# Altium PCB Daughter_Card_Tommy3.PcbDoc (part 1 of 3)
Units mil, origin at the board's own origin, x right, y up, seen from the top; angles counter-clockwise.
Board outline 2032.68 x 3237.01 mil, 8 copper layers (Top Layer, GND, AUX Routing (LVDS), 2.5V, AUX Route Vert, AUX Route Horz, GND (Plane2), Bottom Layer), stack 61.2 mil thick; 218 components, 194 nets, 1097 pads, 500 vias.
Unrouted connection lines stored in the file: 161.
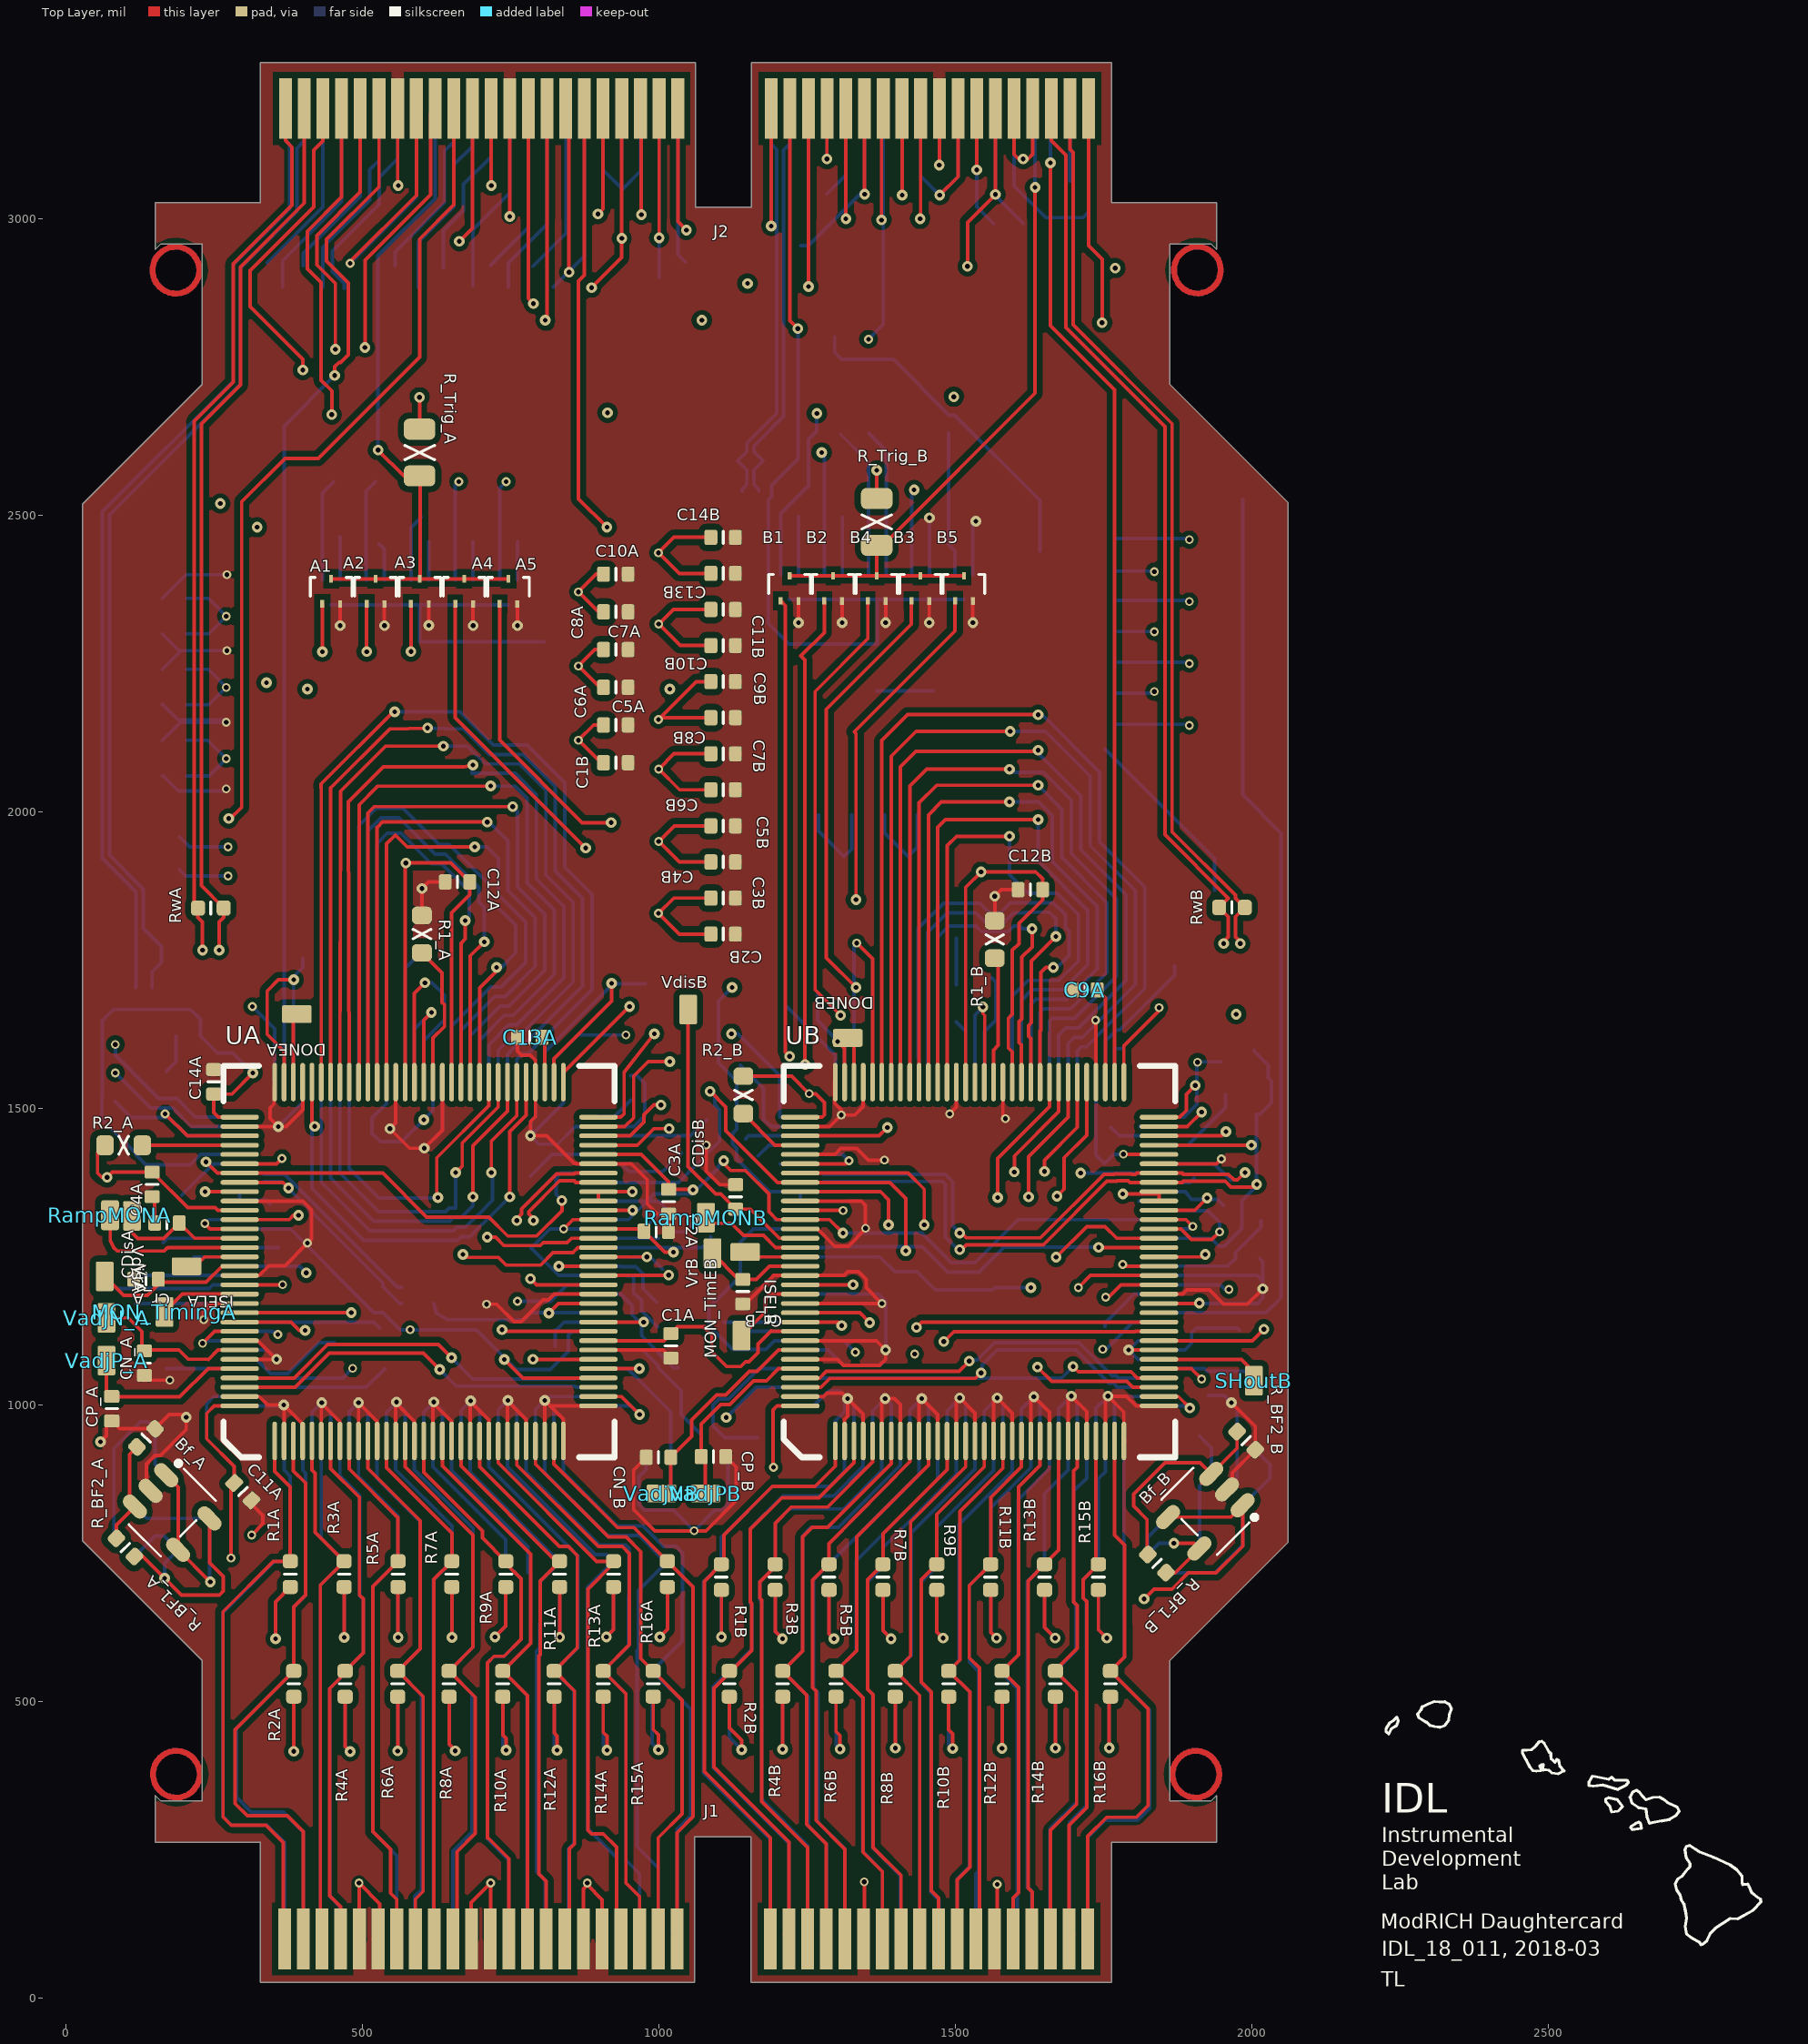
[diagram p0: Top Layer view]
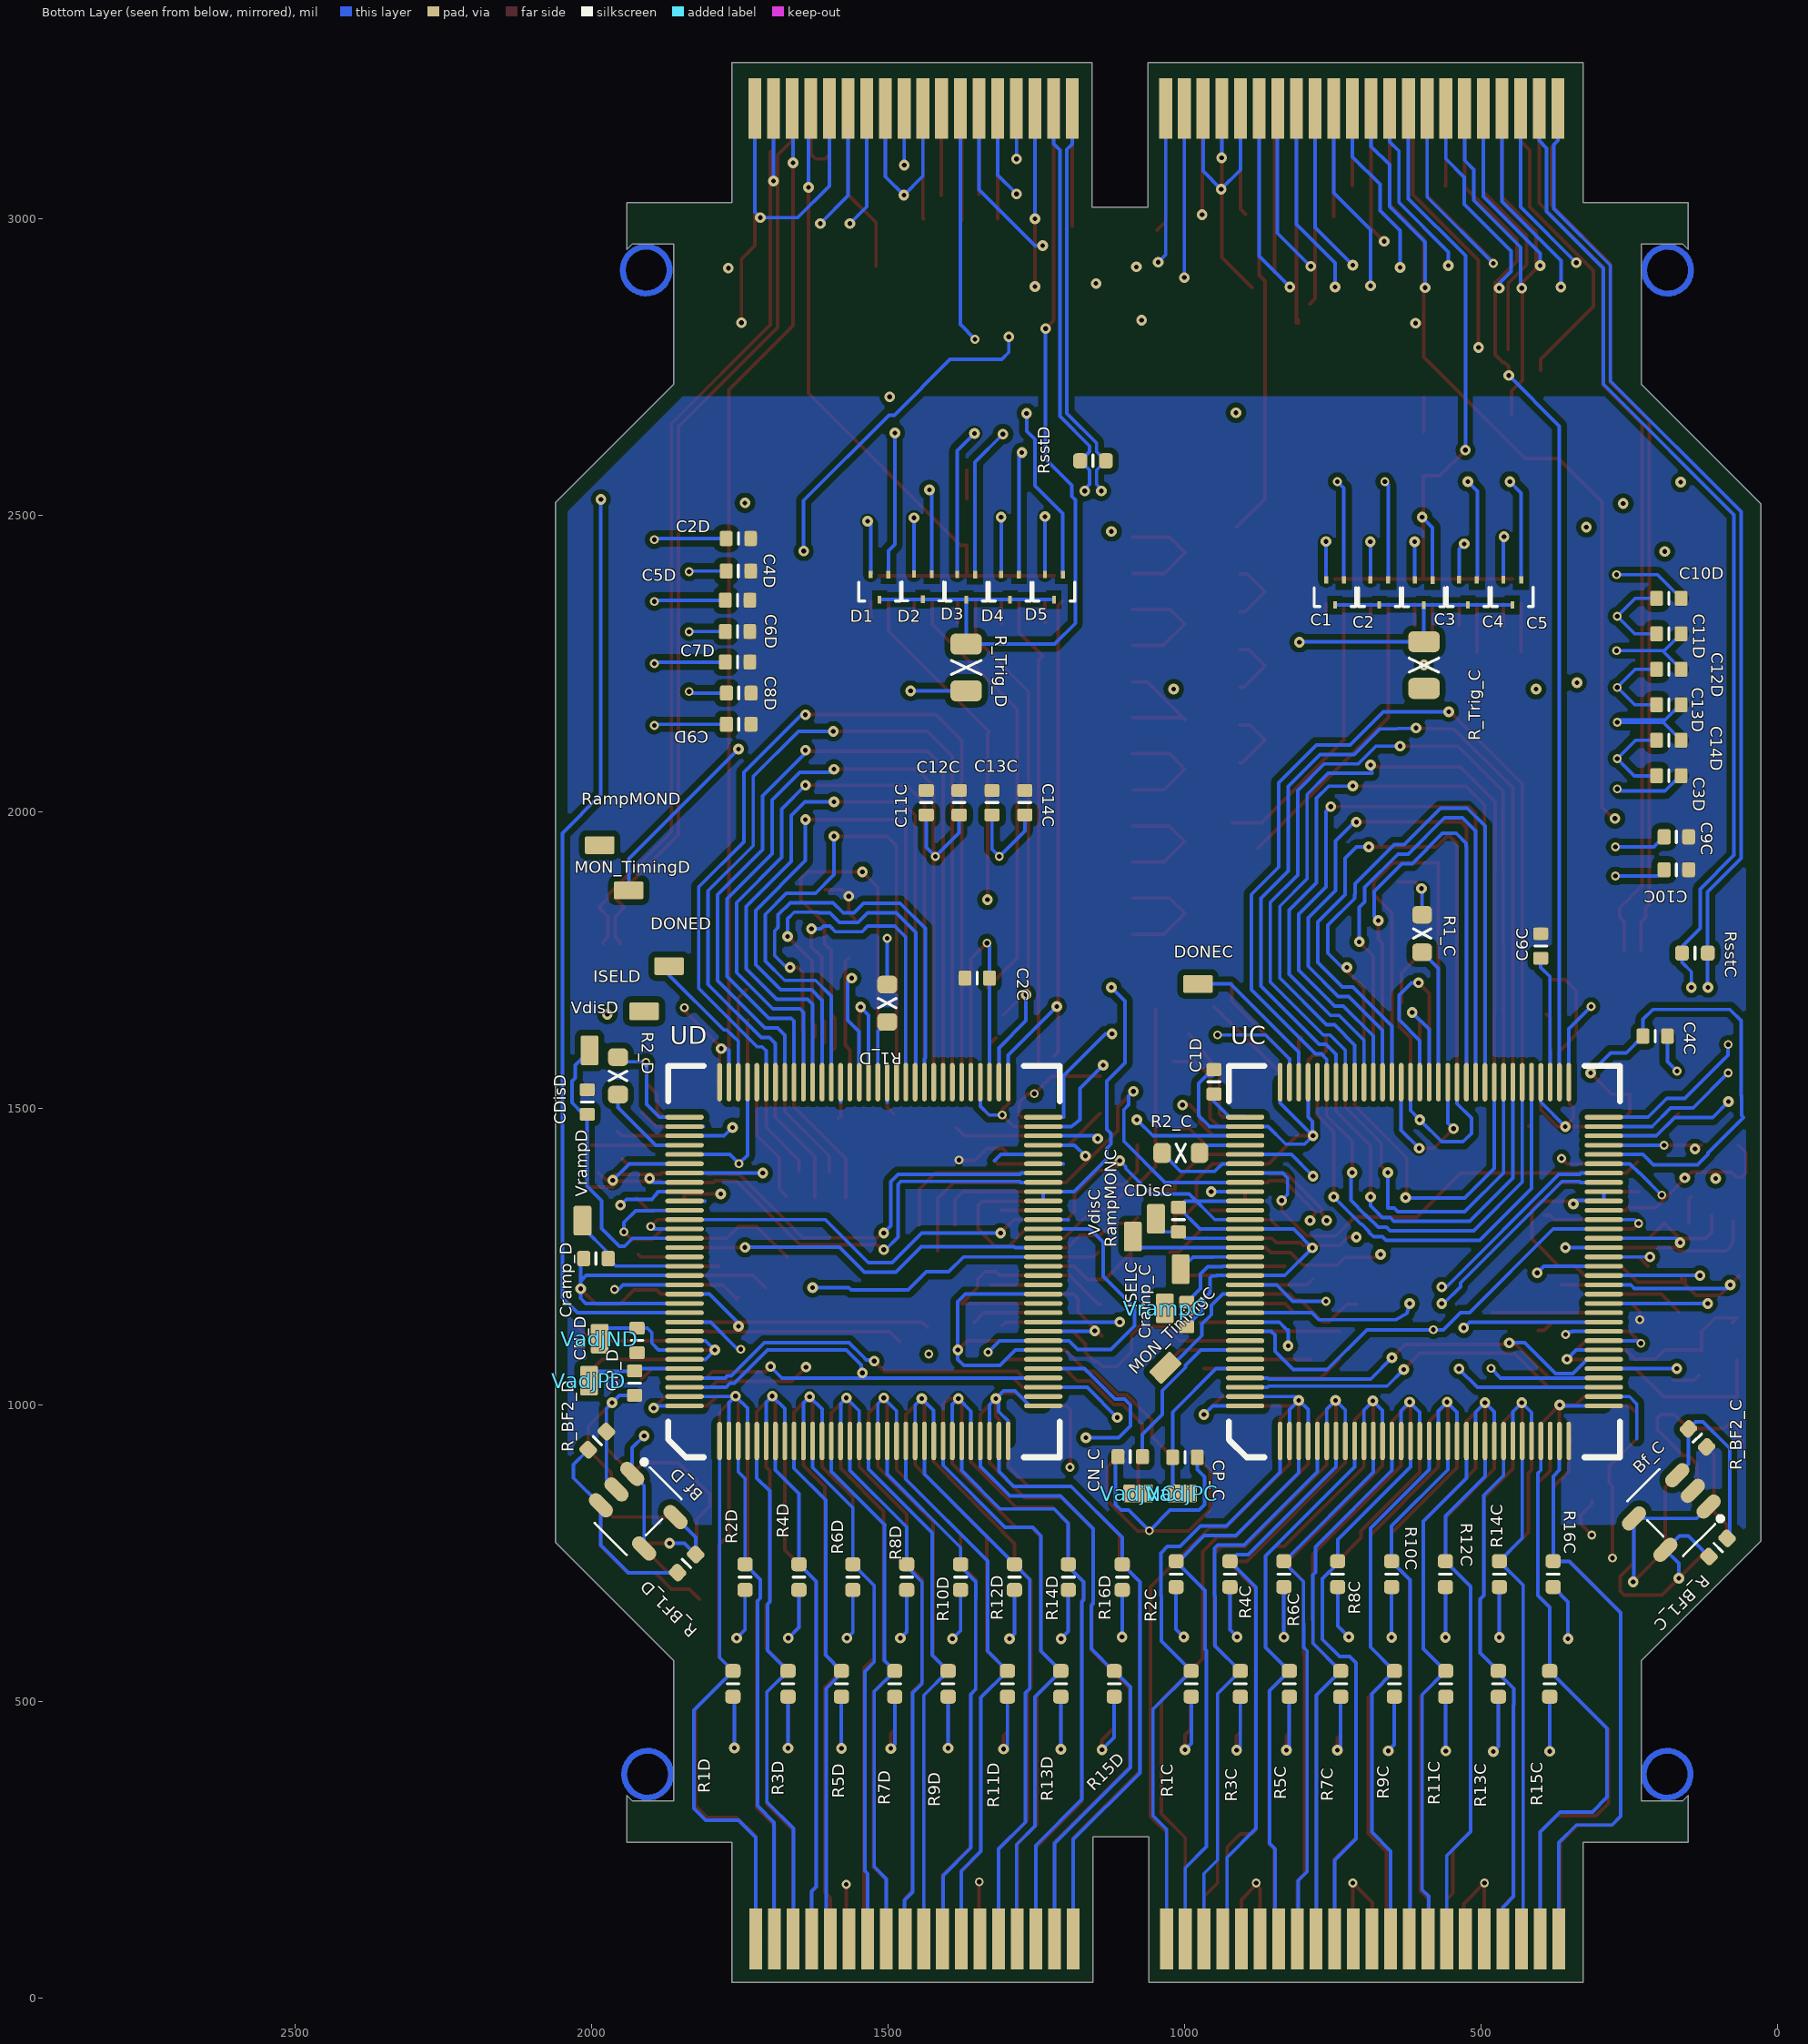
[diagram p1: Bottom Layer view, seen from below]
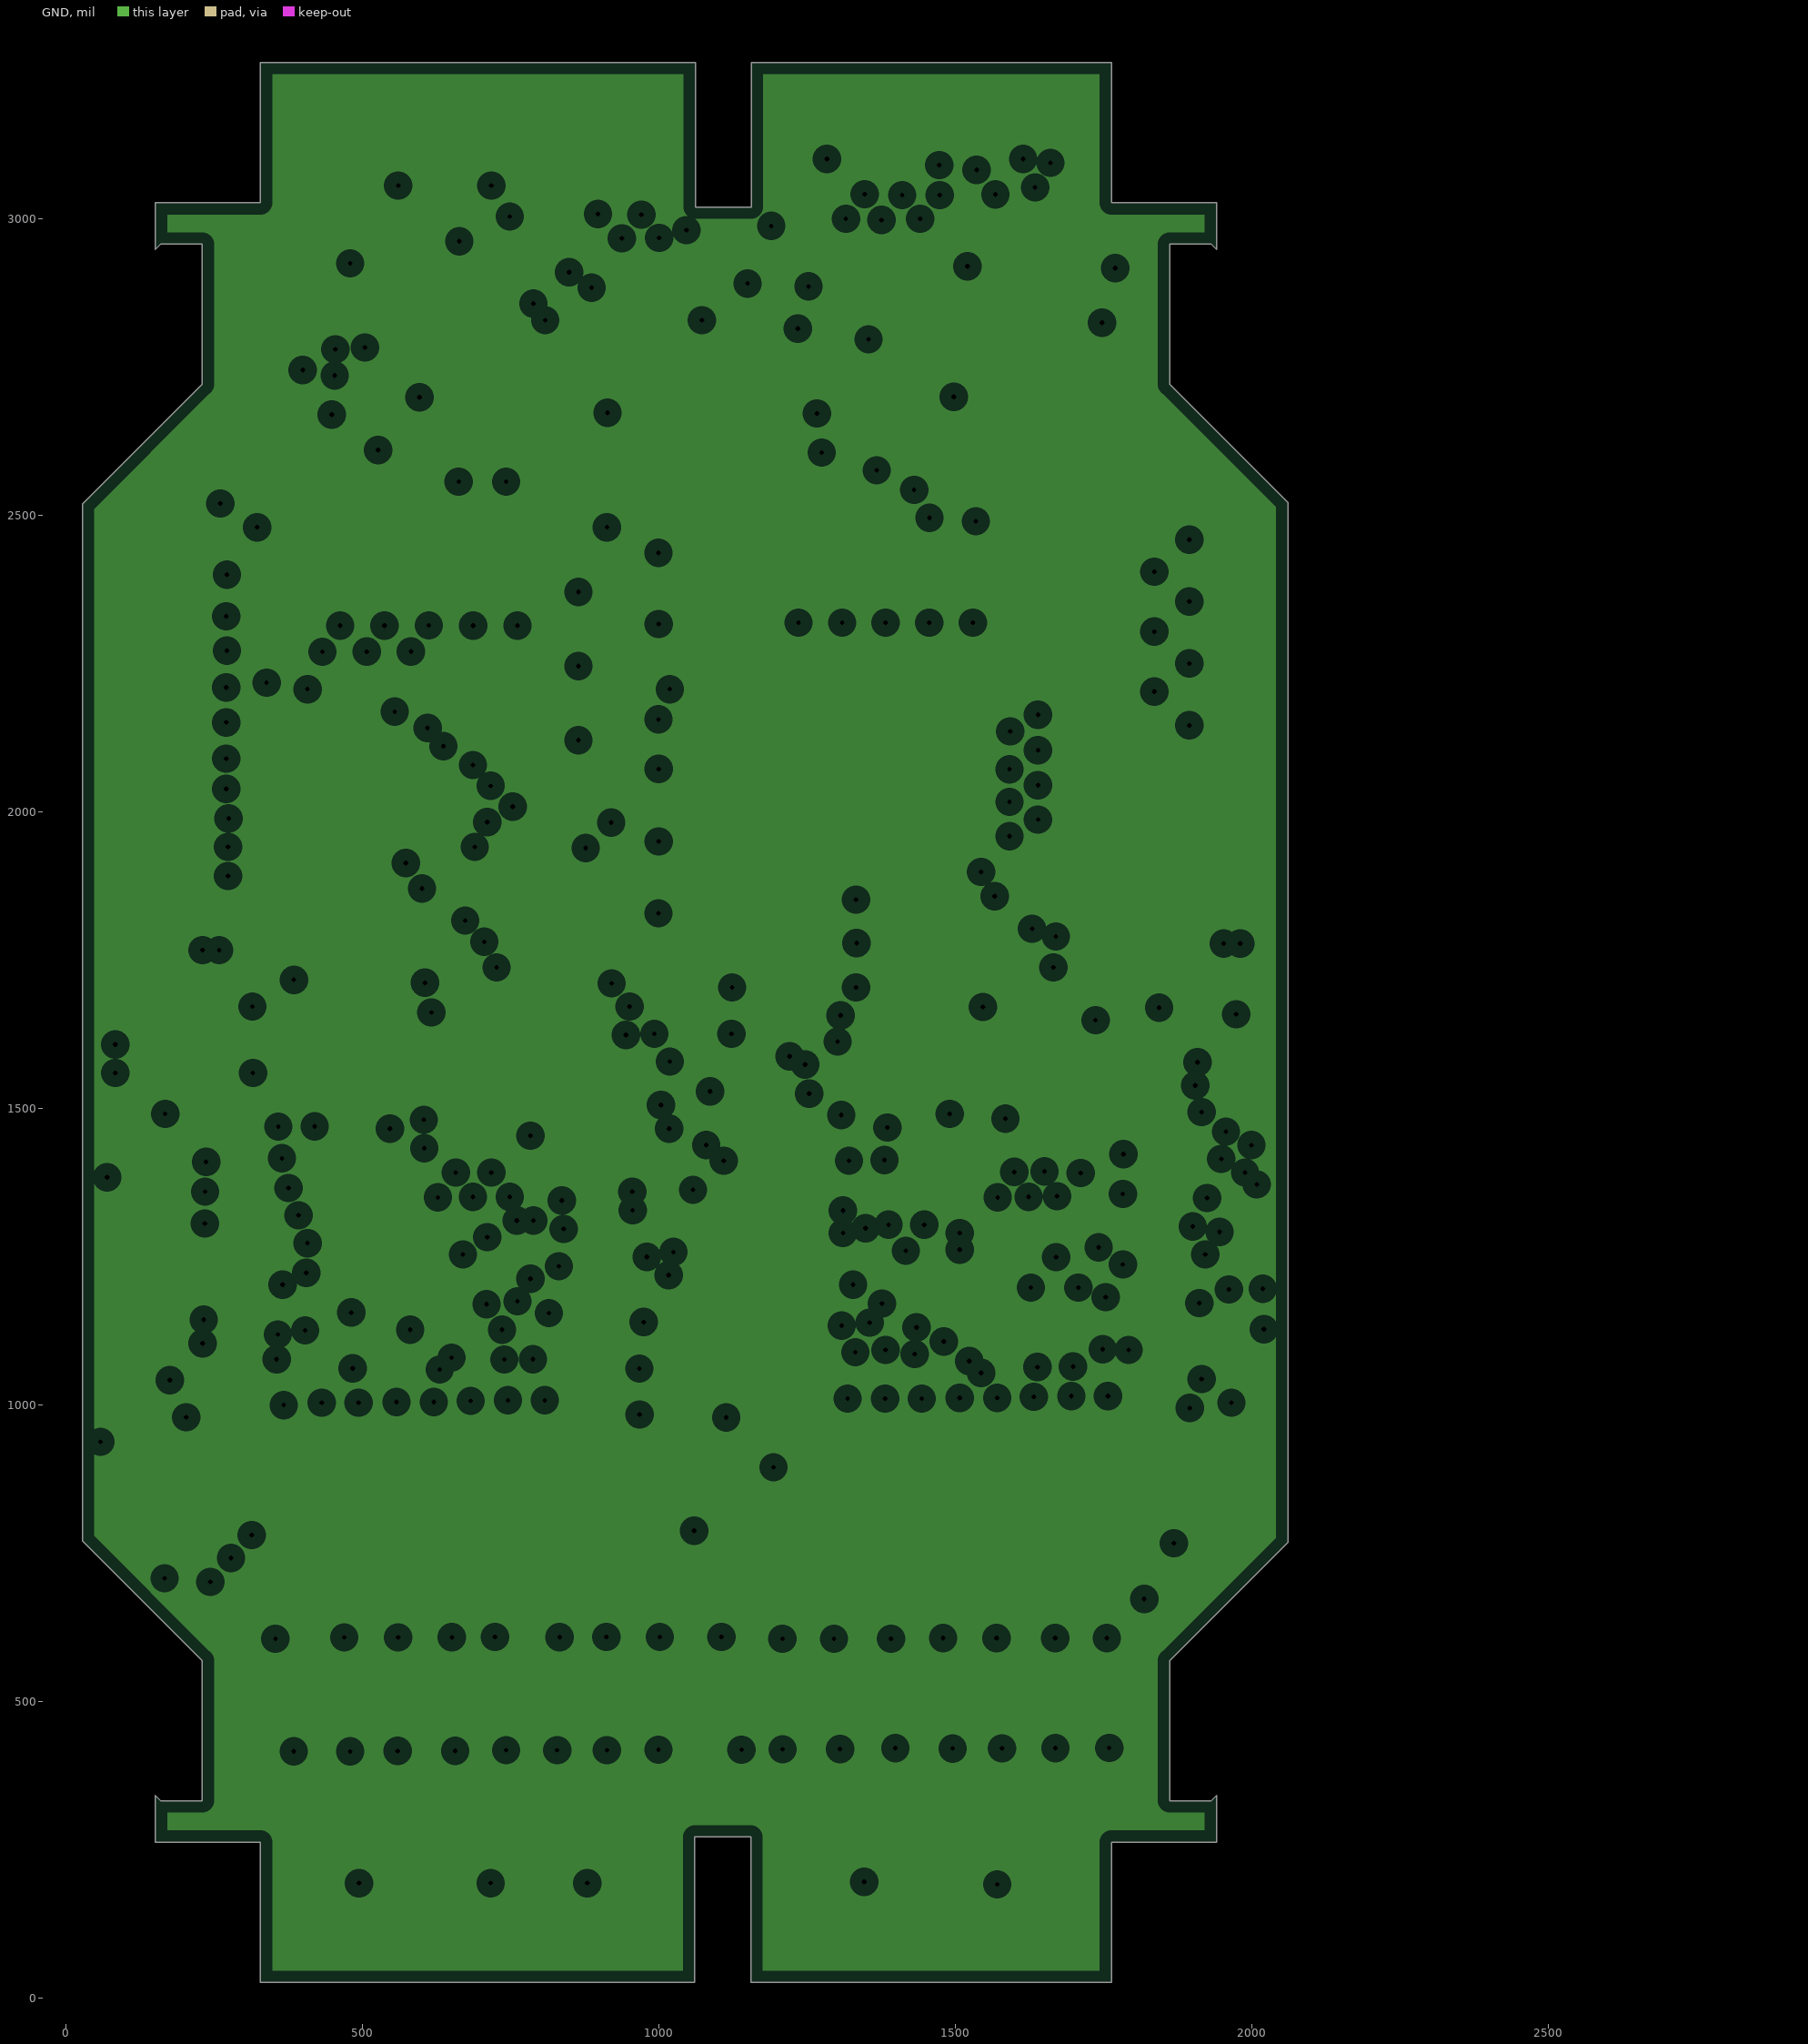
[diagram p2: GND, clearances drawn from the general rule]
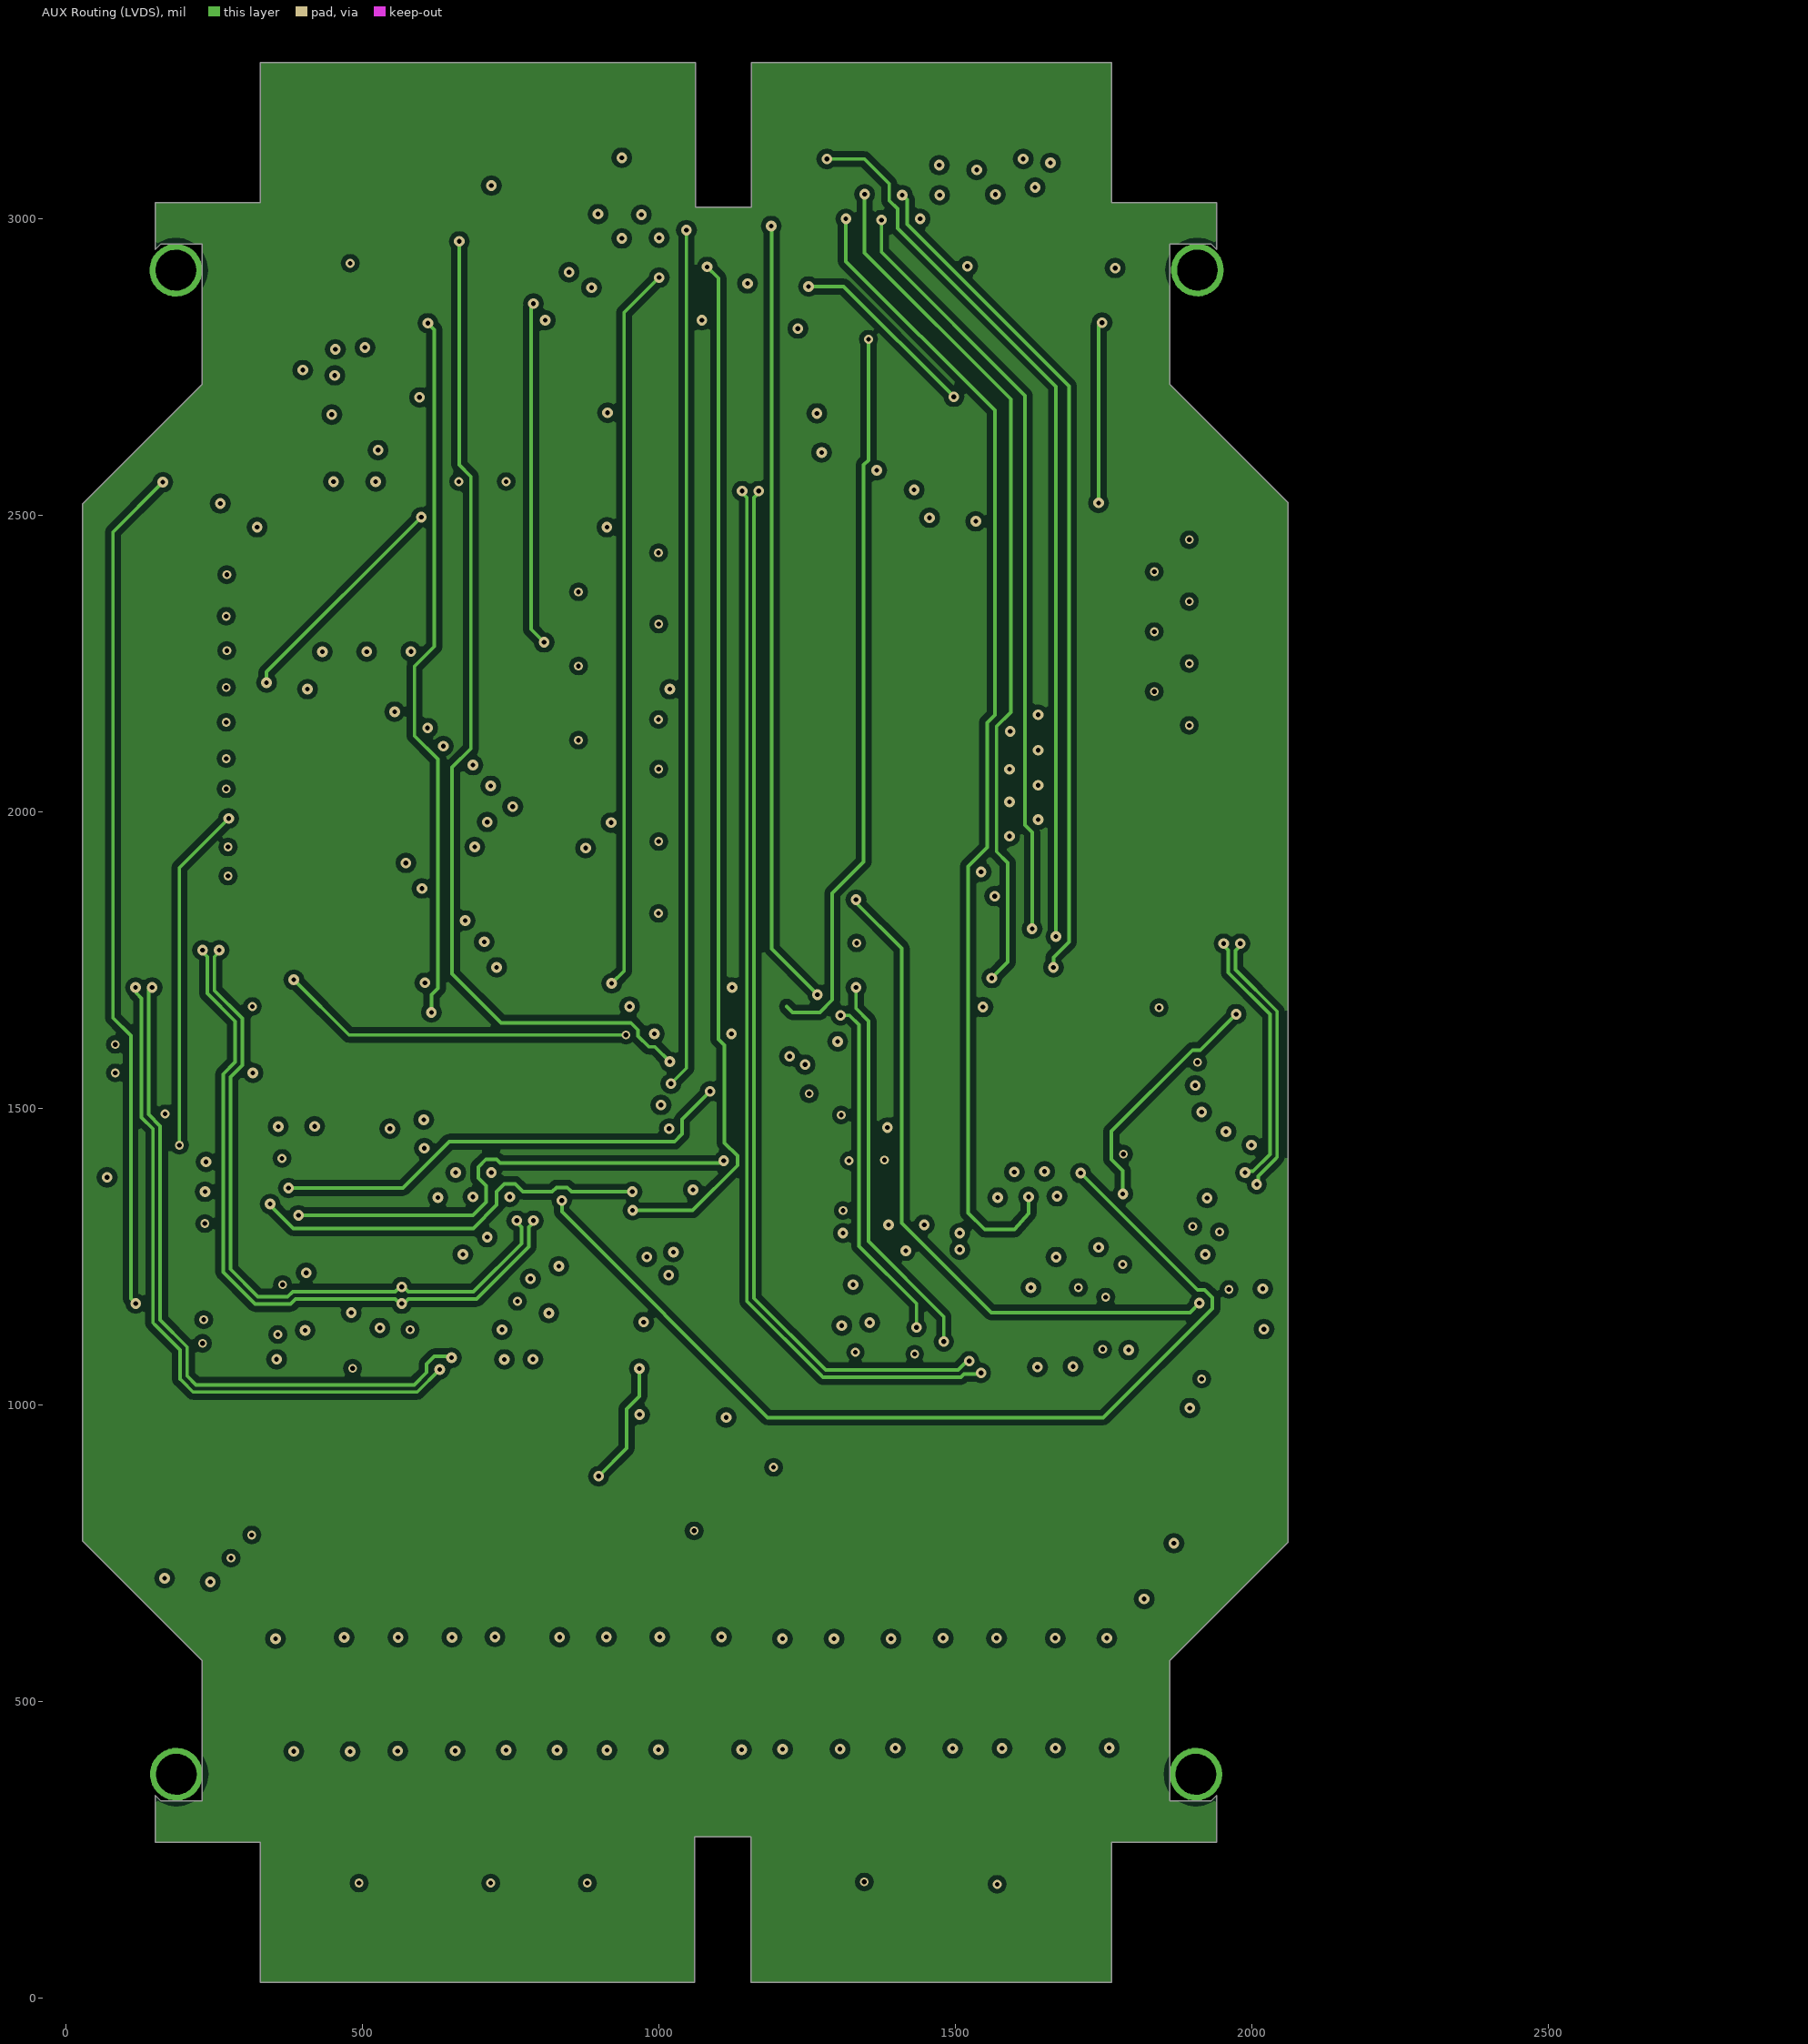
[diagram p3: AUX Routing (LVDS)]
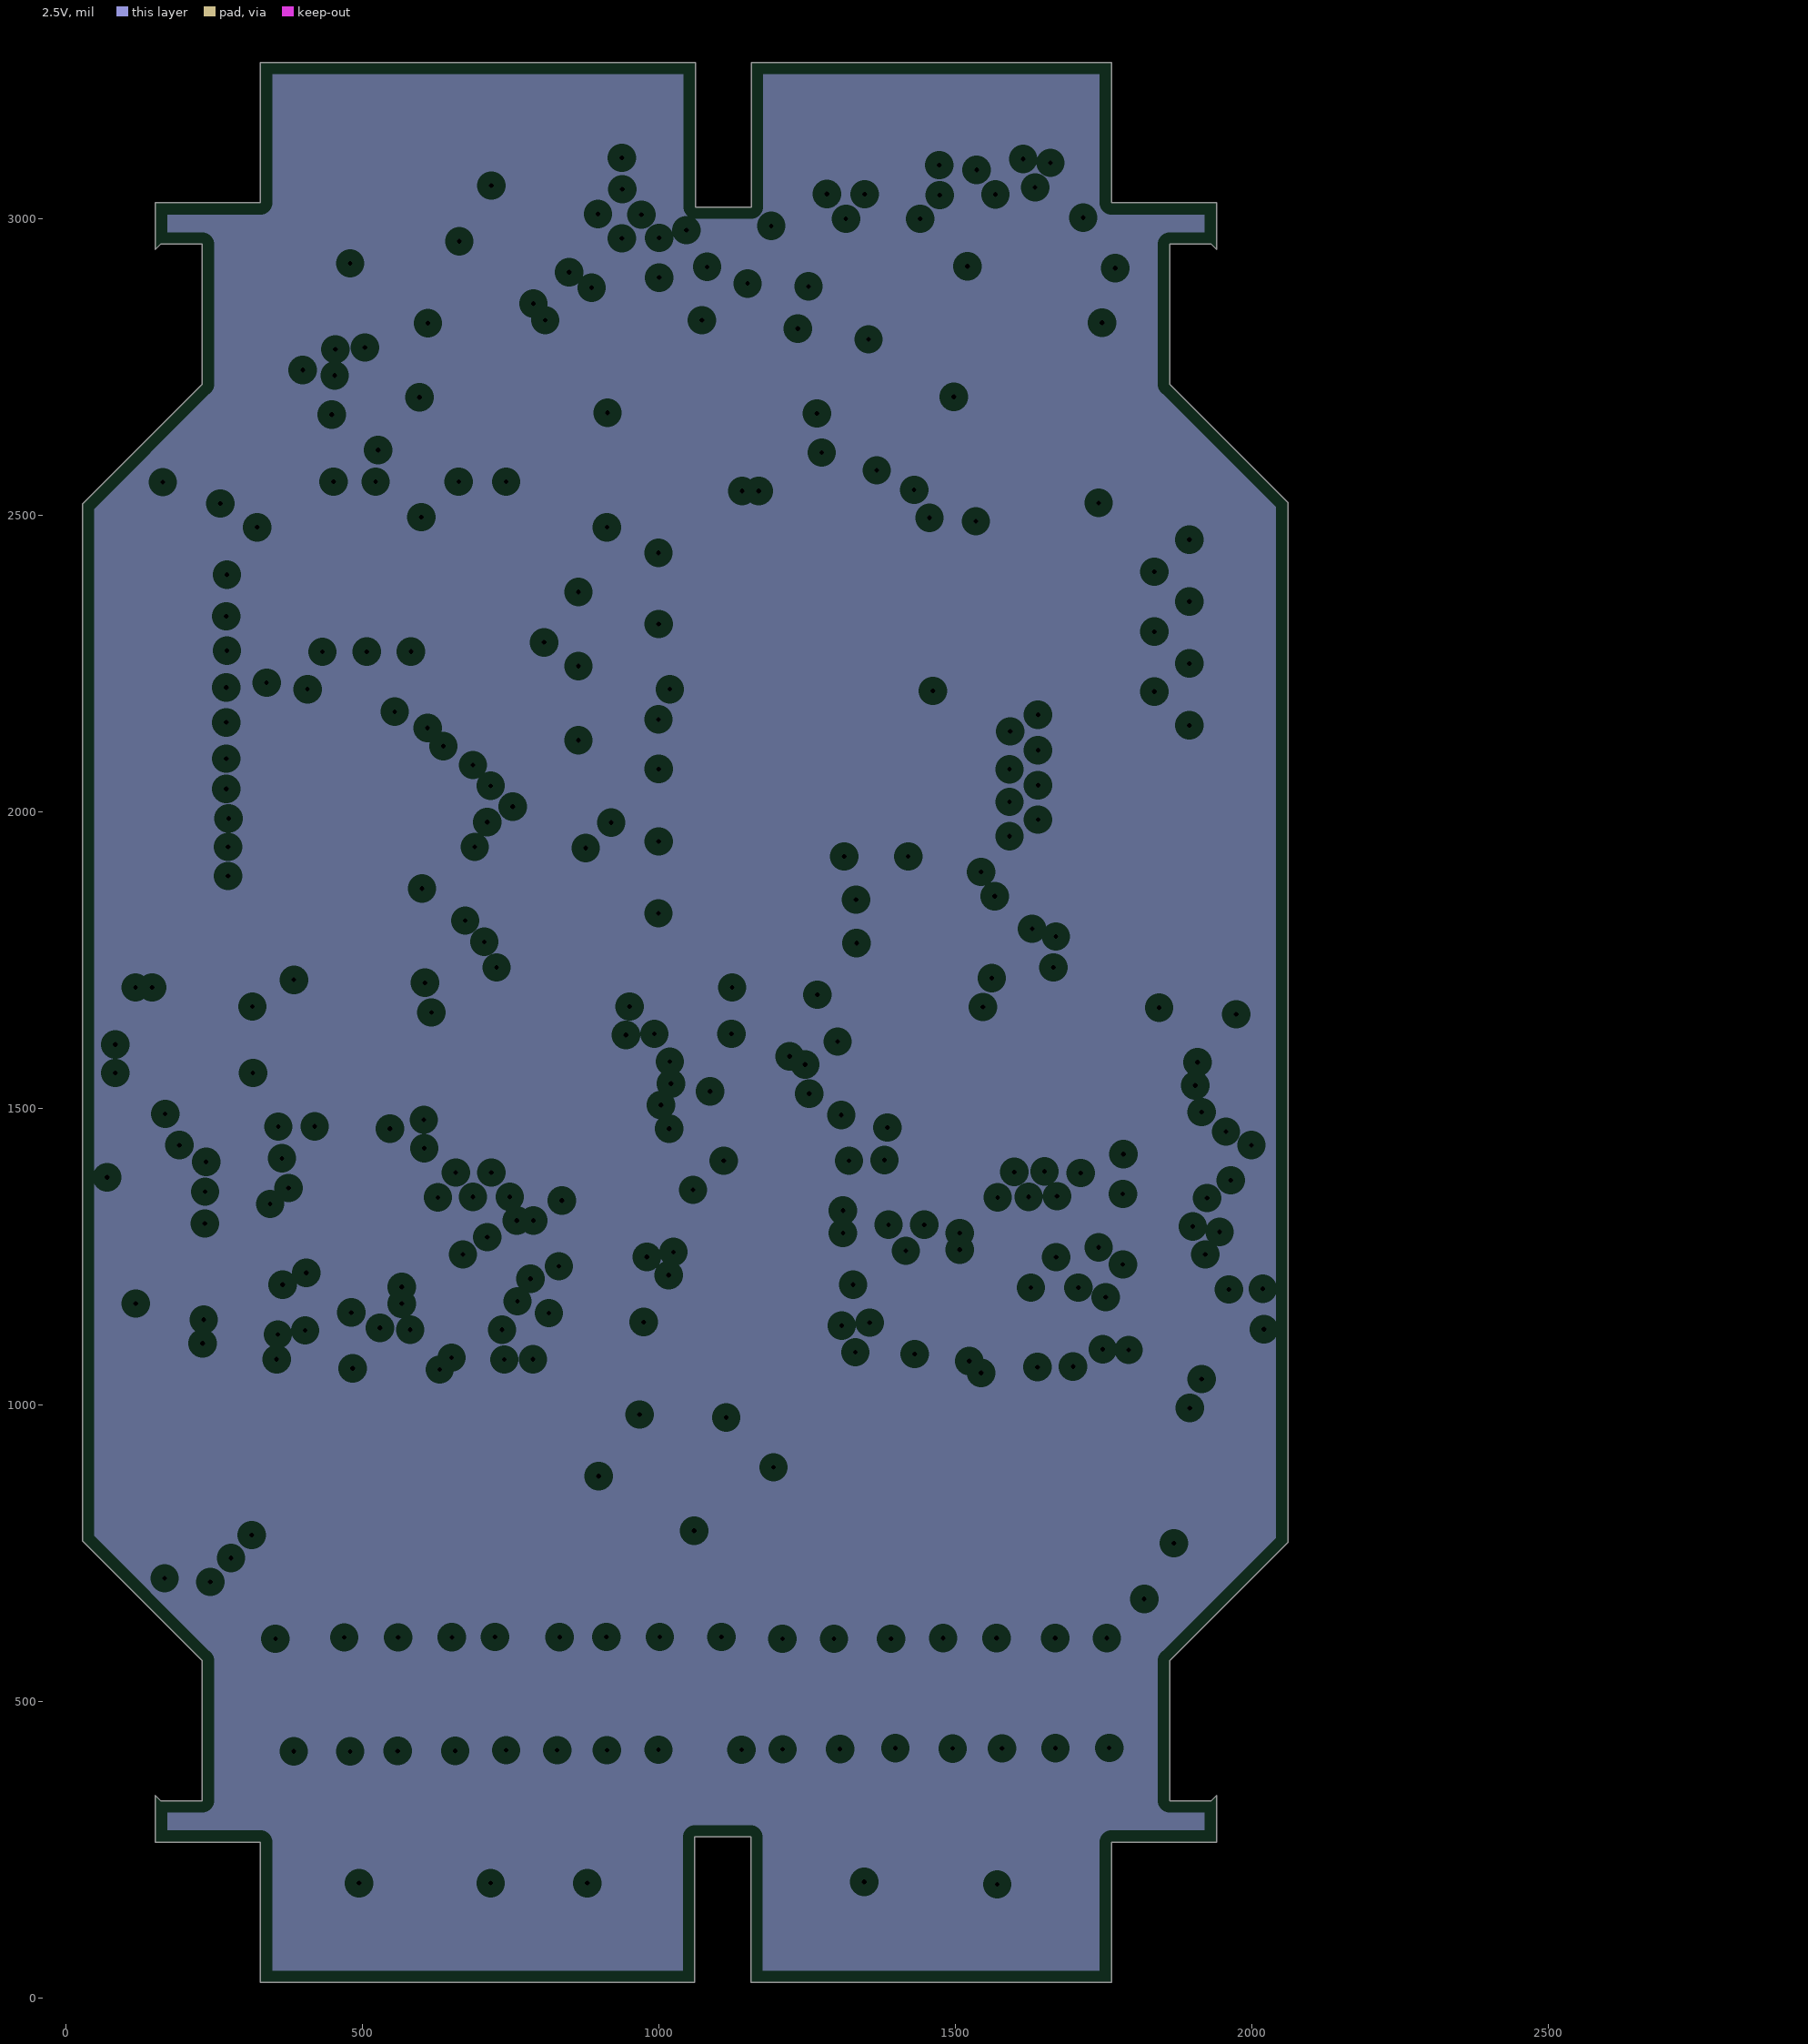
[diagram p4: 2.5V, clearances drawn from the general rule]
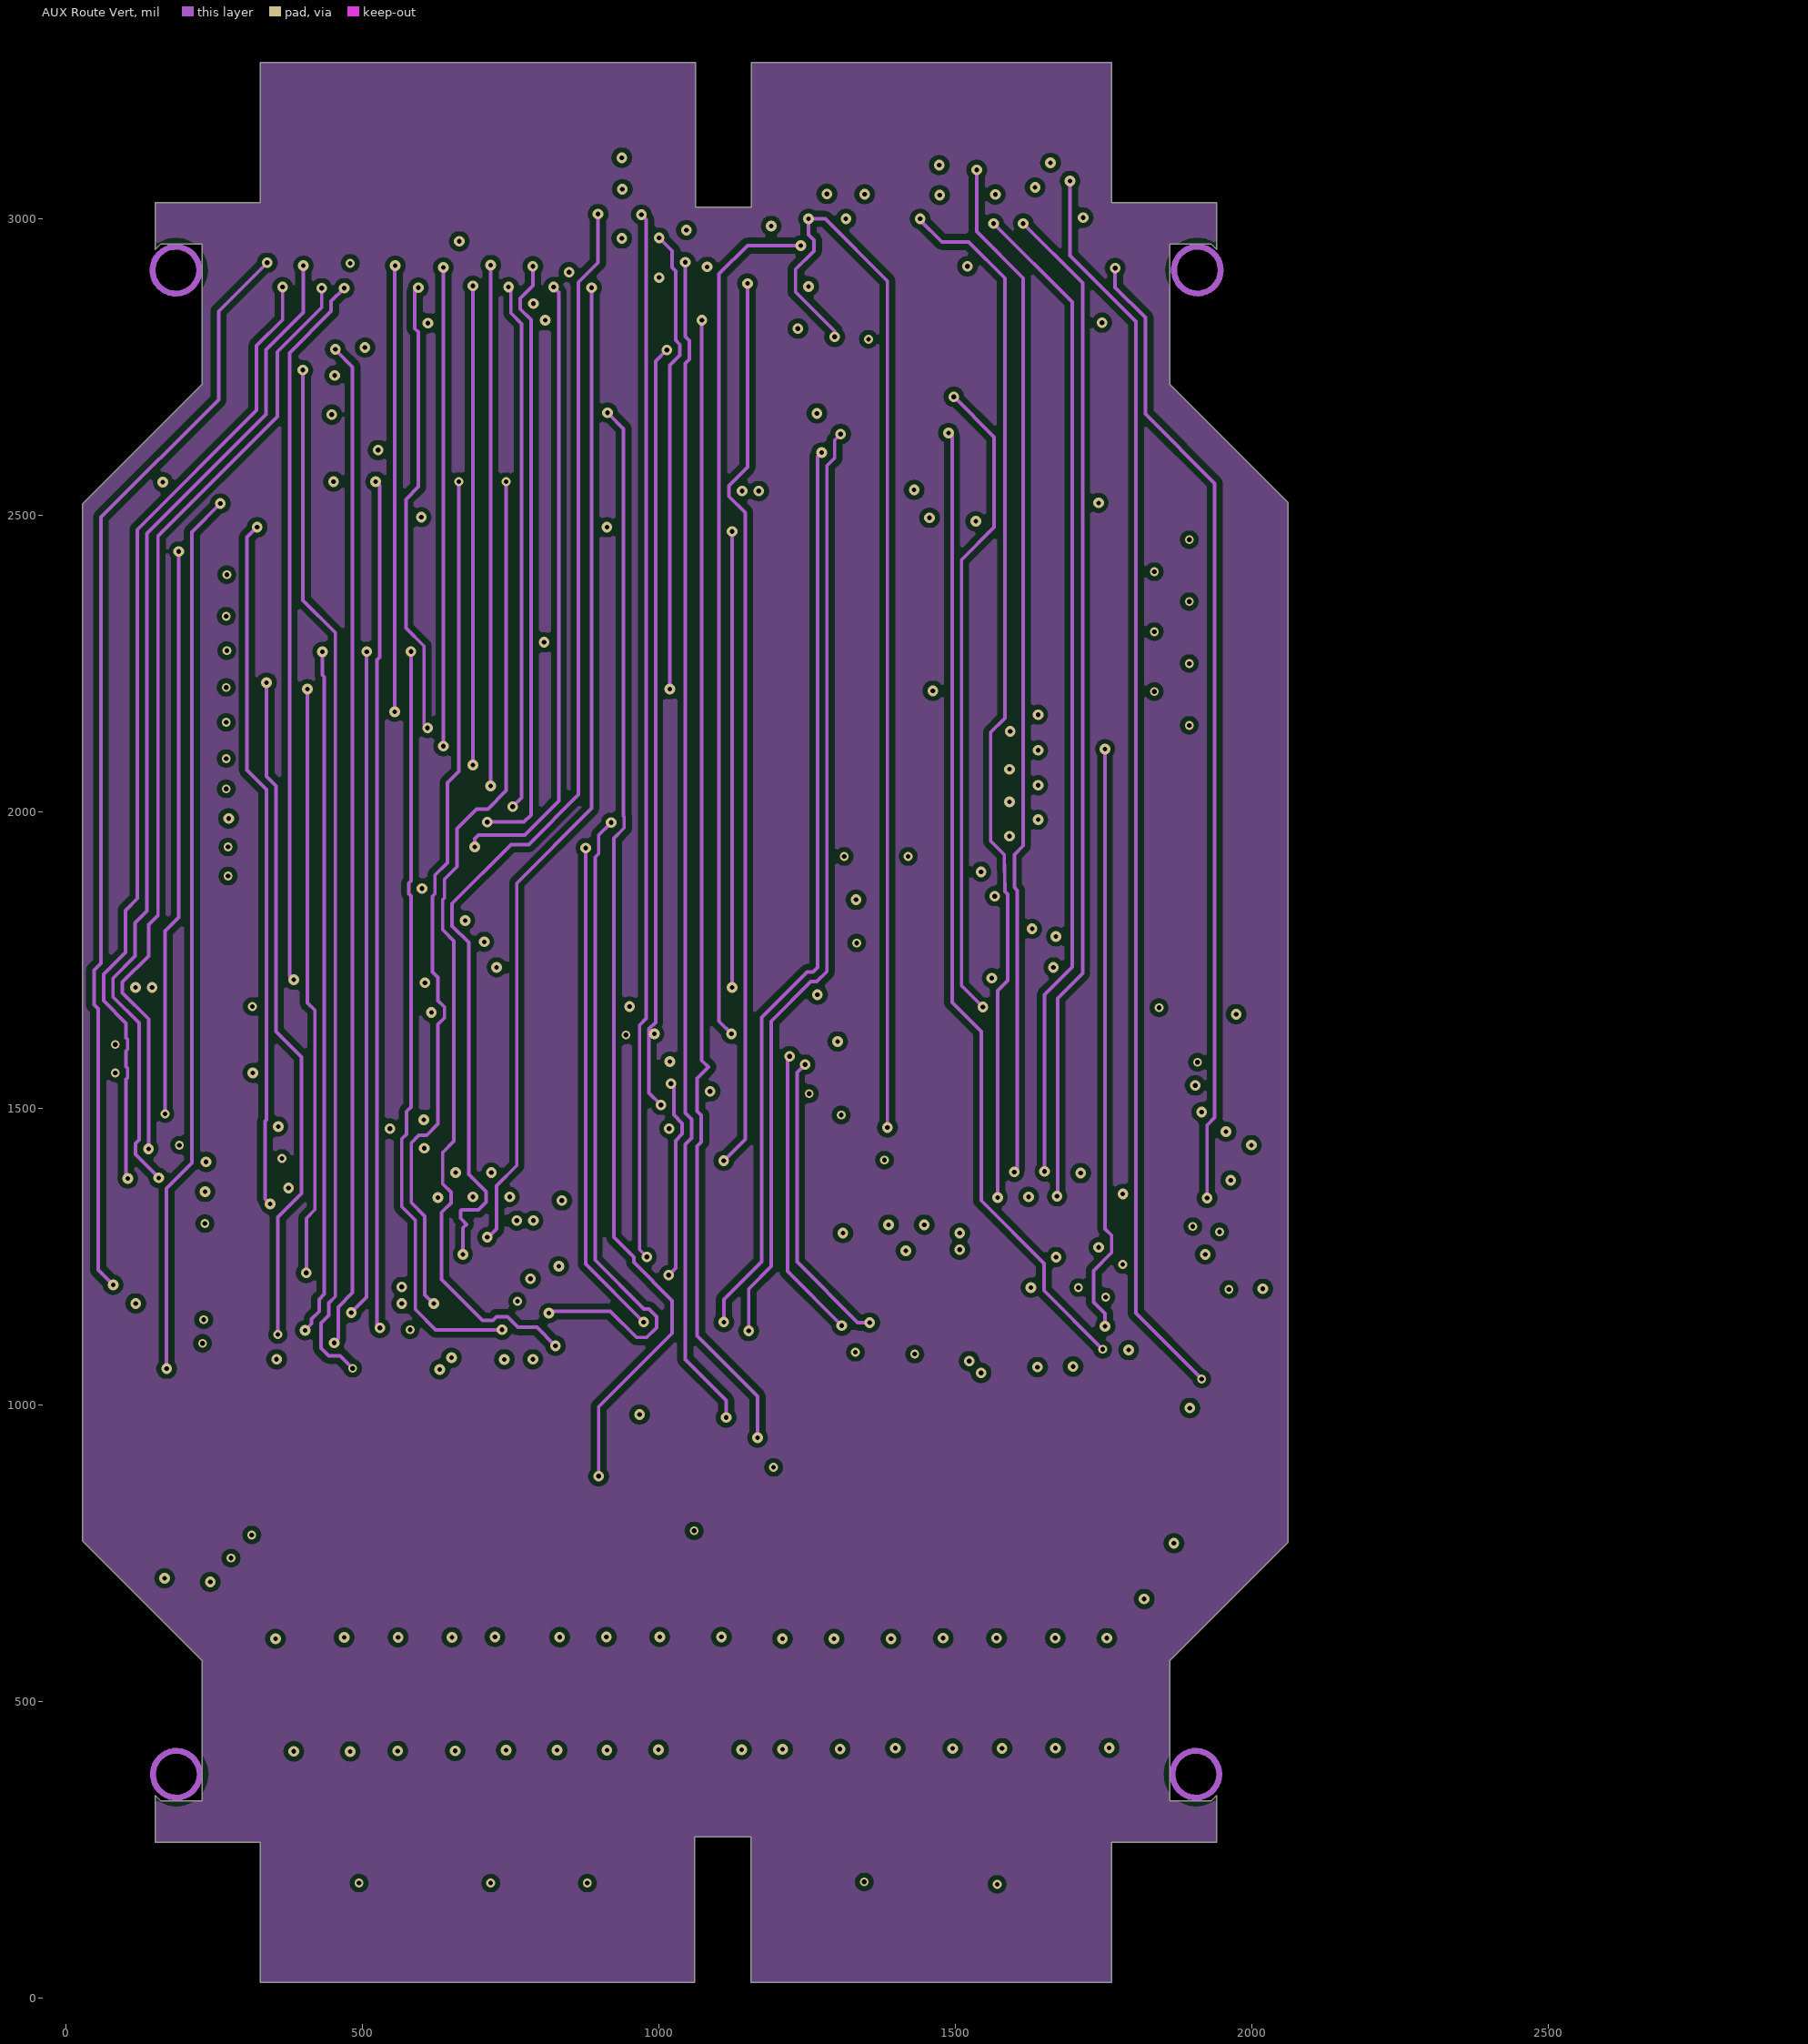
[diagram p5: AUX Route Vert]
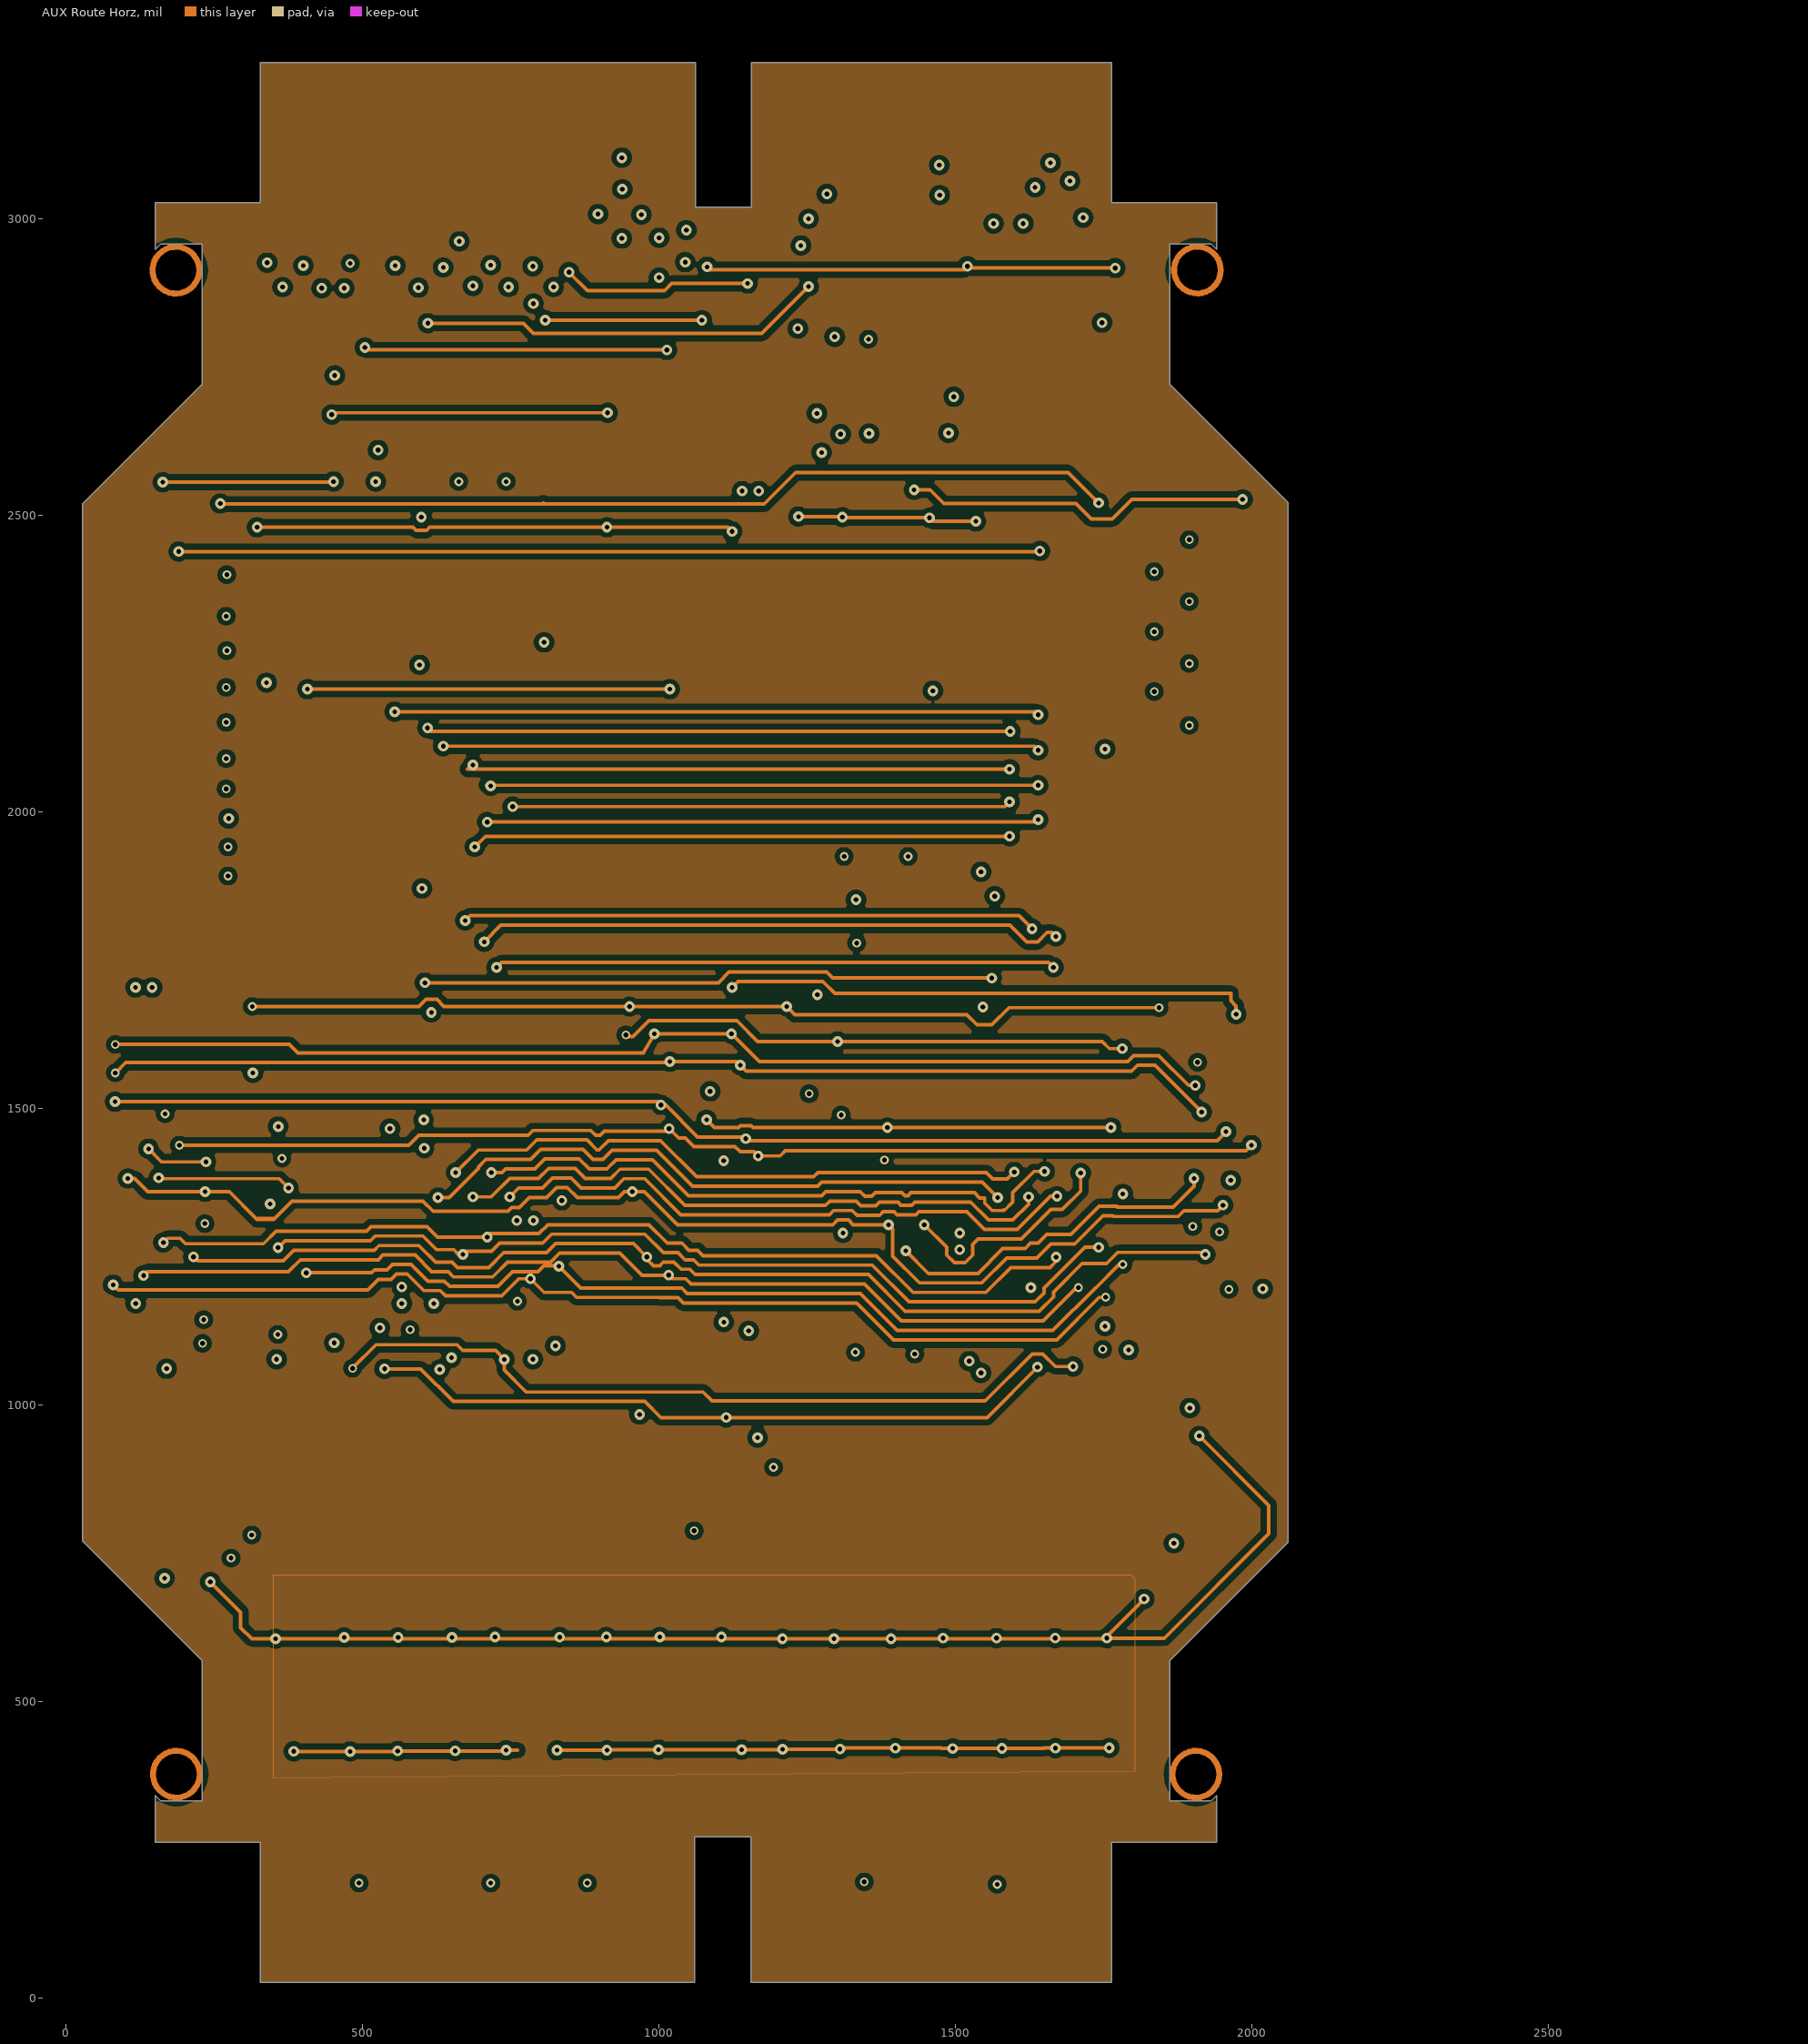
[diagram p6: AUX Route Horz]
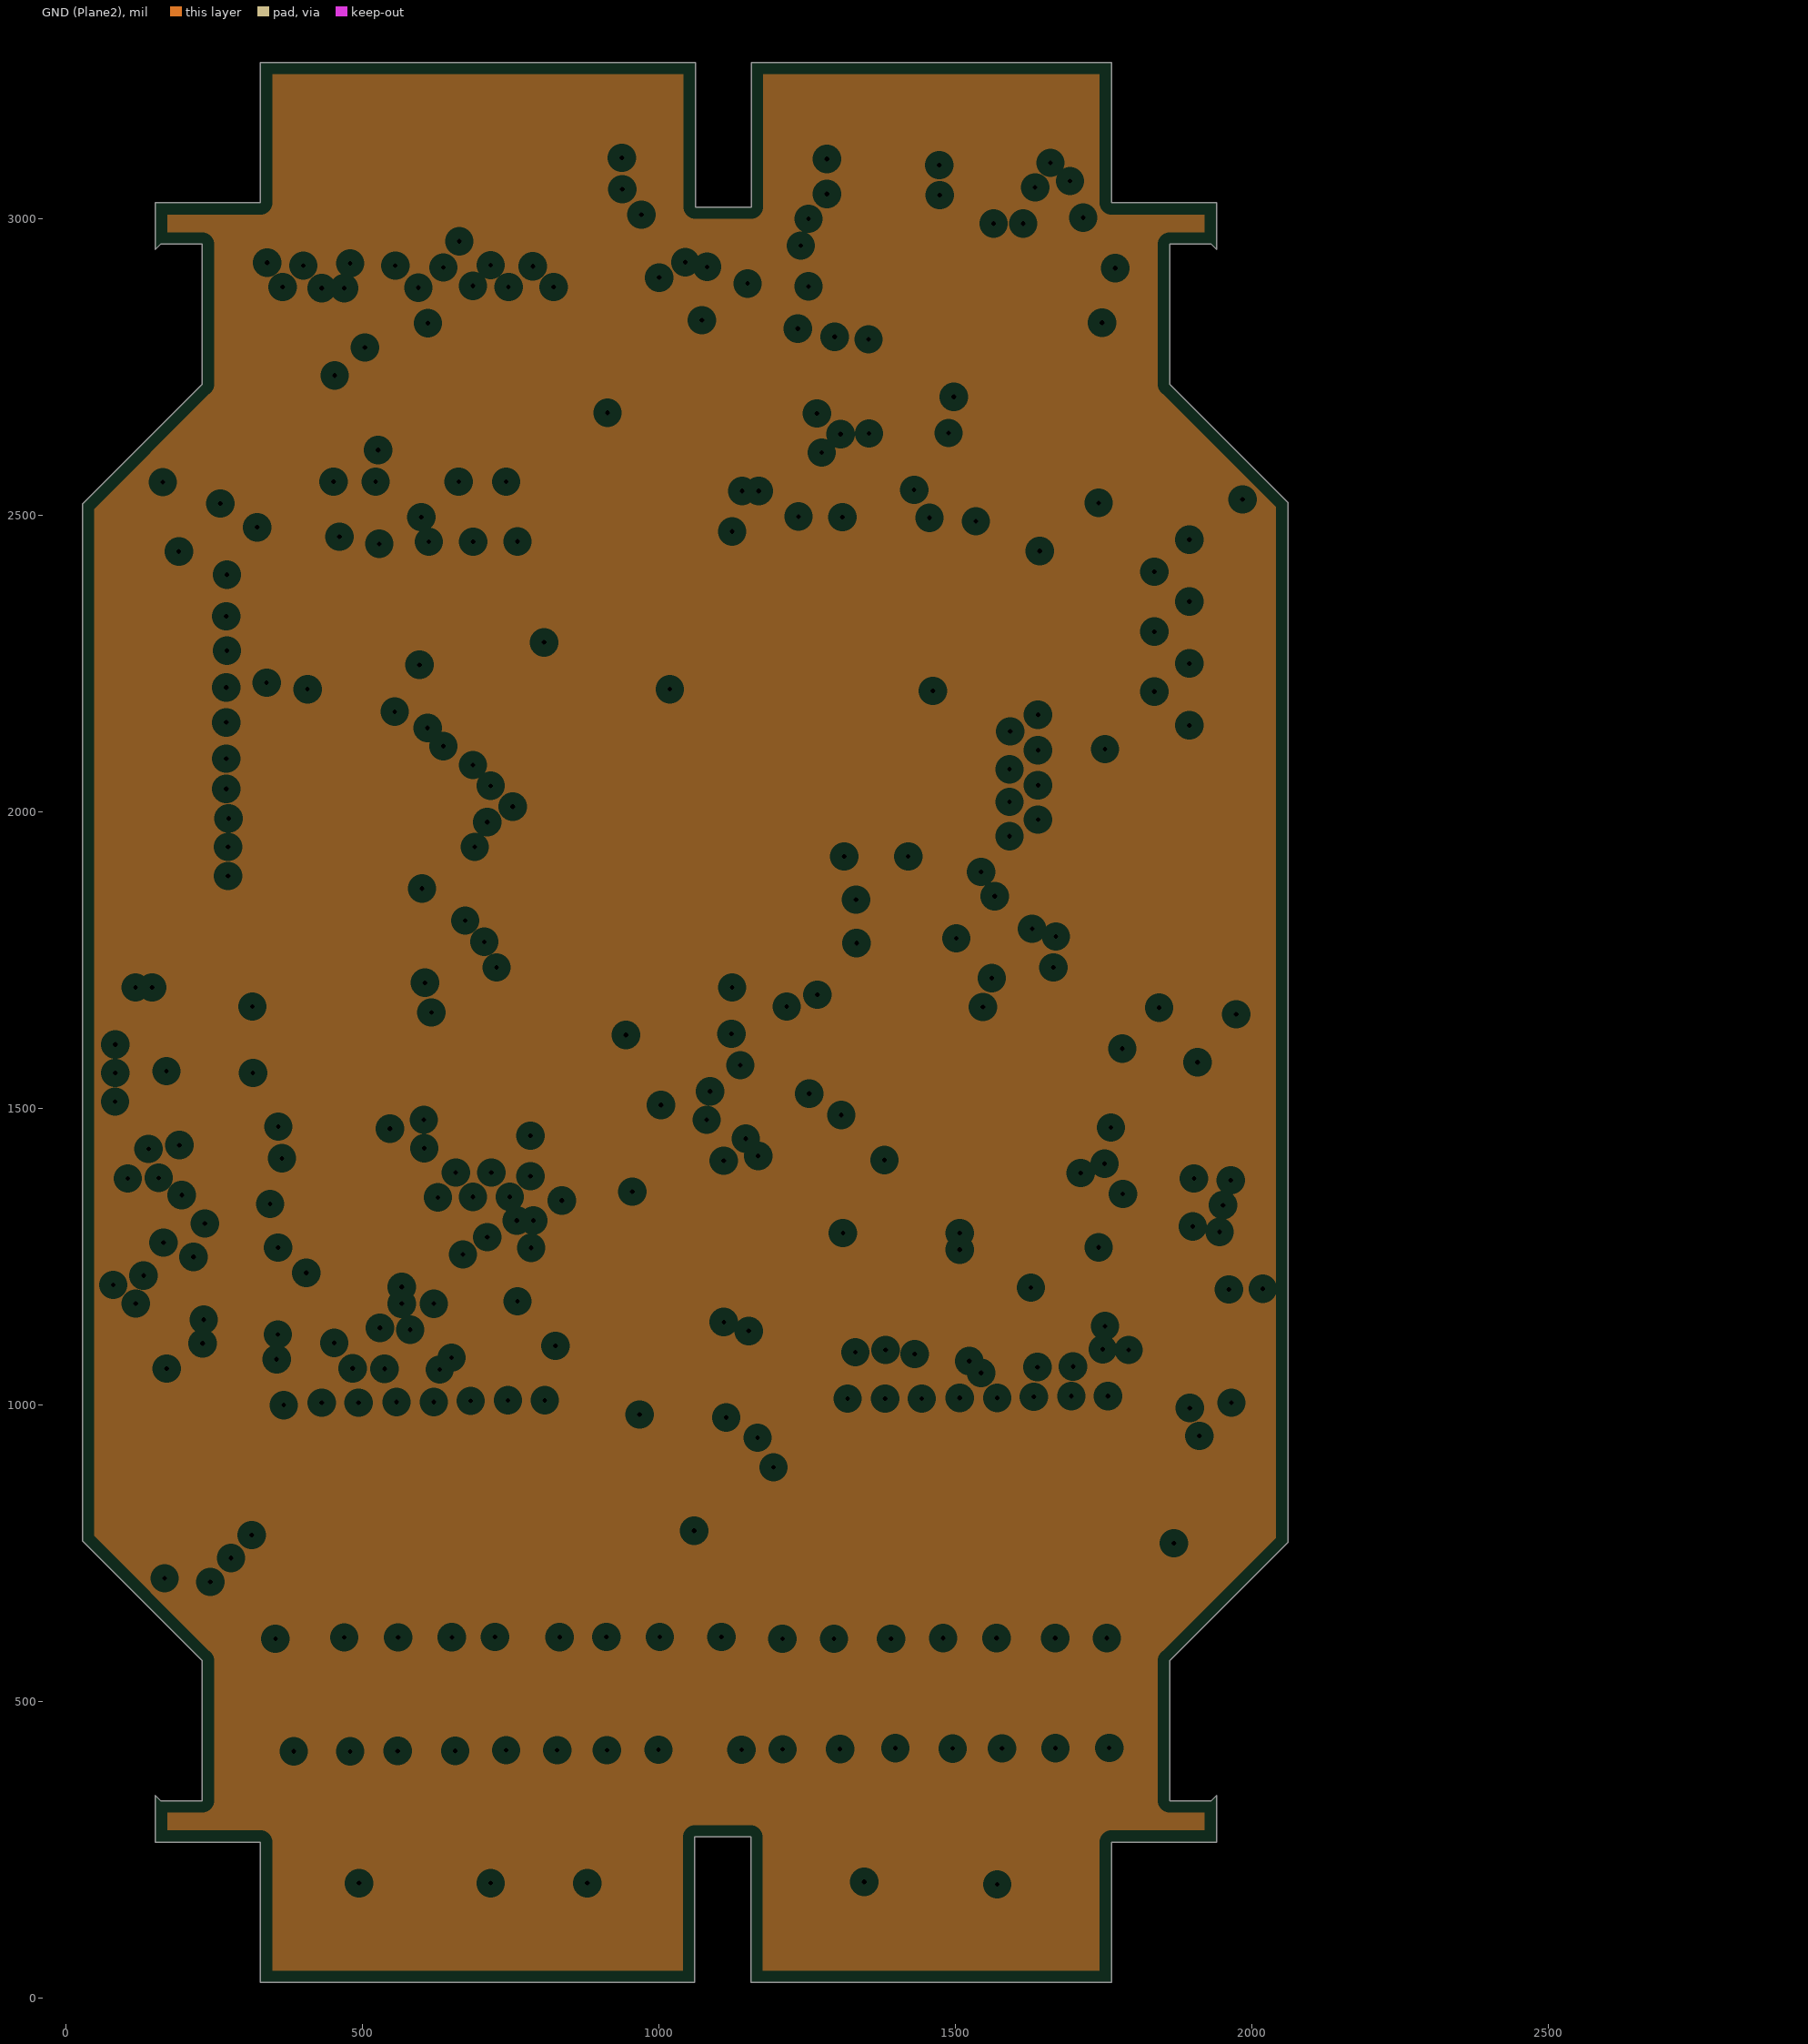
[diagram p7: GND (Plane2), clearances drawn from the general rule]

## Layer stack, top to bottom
Top Solder: solder mask 0.4, Solder Resist, Dk 3.5
Top Layer: signal copper 1.4
Dielectric 1: dielectric 6, FR-4, Dk 4.8
GND: plane copper 1.4
Dielectric3: dielectric 7, FR-4, Dk 4.8
AUX Routing (LVDS): signal copper 1.4
Dielectric4: dielectric 8, FR-4, Dk 4.8
2.5V: plane copper 1.4
Dielectric5: dielectric 8, FR-4, Dk 4.8
AUX Route Vert: signal copper 1.4
Dielectric2: dielectric 8, FR-4, Dk 4.8
AUX Route Horz: signal copper 1.4
Dielectric6: dielectric 7, FR-4, Dk 4.8
GND (Plane2): plane copper 1.4
Dielectric8: dielectric 6, FR-4, Dk 4.8
Bottom Layer: signal copper 1.4
Bottom Solder: solder mask 0.4, Solder Resist, Dk 3.5

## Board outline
1061.02,3263.58 1061.02,3019.88 1155.51,3019.88 1155.51,3263.58 1762.8,3263.58 1762.8,3027.36 1939.96,3027.36 1939.96,2948.62 1931.3,2957.28 1861.22,2957.28 1861.22,2721.06 2060.24,2522.05 2060.24,768.11 1861.22,569.09 1861.22,332.87 1931.3,332.87 1939.96,341.54 1939.96,262.8 1762.8,262.8 1762.8,26.57 1154.53,26.57 1154.53,271.85 1060.04,271.85 1060.04,26.57 327.76,26.57 327.76,262.8 150.59,262.8 150.59,341.54 159.25,332.87 229.33,332.87 229.33,569.09 27.56,770.87 27.56,2519.29 229.33,2721.06 229.33,2957.28 159.25,2957.28 150.59,2948.62 150.59,3027.36 327.76,3027.36 327.76,3263.58

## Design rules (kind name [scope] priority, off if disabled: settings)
Clearance [All] p1: gap=10 ignorepadtopadclearanceinfootprint=FALSE except(0: Arc-Hole Track-Hole SMDPad-Hole THPad-Hole Via-Hole Fill-Hole Poly-Hole Region-Hole Text-Hole; 8: Via-Fill Via-Poly Via-Region)
DiffPairsRouting "Schematic Differential Pairs Routing_9" [InNet('TX_AC_SSTin_N')] p1: maxlimit=6 minlimit=6 mostfreqgap=6 toplayer_minwidth=6 toplayer_maxwidth=6 toplayer_prefwidth=6 midlayer1_minwidth=6 midlayer1_maxwidth=6 midlayer1_prefwidth=6 midlayer2_minwidth=6 midlayer2_maxwidth=6 midlayer2_prefwidth=6 midlayer3_minwidth=6 midlayer3_maxwidth=6 midlayer3_prefwidth=6 bottomlayer_minwidth=6 bottomlayer_maxwidth=6 bottomlayer_prefwidth=6 maxuncoupledlength=500
DiffPairsRouting "Schematic Differential Pairs Routing_8" [InNet('TX_AC_SSTin_N')] p2: maxlimit=6 minlimit=6 mostfreqgap=6 toplayer_minwidth=6 toplayer_maxwidth=6 toplayer_prefwidth=6 midlayer1_minwidth=6 midlayer1_maxwidth=6 midlayer1_prefwidth=6 midlayer2_minwidth=6 midlayer2_maxwidth=6 midlayer2_prefwidth=6 midlayer3_minwidth=6 midlayer3_maxwidth=6 midlayer3_prefwidth=6 bottomlayer_minwidth=6 bottomlayer_maxwidth=6 bottomlayer_prefwidth=6 maxuncoupledlength=500
DiffPairsRouting "Schematic Differential Pairs Routing_7" [InNet('TX_AC_WL_CLK_N')] p3: maxlimit=6 minlimit=6 mostfreqgap=6 toplayer_minwidth=6 toplayer_maxwidth=6 toplayer_prefwidth=6 midlayer1_minwidth=6 midlayer1_maxwidth=6 midlayer1_prefwidth=6 midlayer2_minwidth=6 midlayer2_maxwidth=6 midlayer2_prefwidth=6 midlayer3_minwidth=6 midlayer3_maxwidth=6 midlayer3_prefwidth=6 bottomlayer_minwidth=6 bottomlayer_maxwidth=6 bottomlayer_prefwidth=6 maxuncoupledlength=500
DiffPairsRouting "Schematic Differential Pairs Routing_6" [InNet('TX_AC_WL_CLK_N')] p4: maxlimit=6 minlimit=6 mostfreqgap=6 toplayer_minwidth=6 toplayer_maxwidth=6 toplayer_prefwidth=6 midlayer1_minwidth=6 midlayer1_maxwidth=6 midlayer1_prefwidth=6 midlayer2_minwidth=6 midlayer2_maxwidth=6 midlayer2_prefwidth=6 midlayer3_minwidth=6 midlayer3_maxwidth=6 midlayer3_prefwidth=6 bottomlayer_minwidth=6 bottomlayer_maxwidth=6 bottomlayer_prefwidth=6 maxuncoupledlength=500
DiffPairsRouting "Schematic Differential Pairs Routing_5" [InNet('TX_AC_SSTin_P')] p5: maxlimit=6 minlimit=6 mostfreqgap=6 toplayer_minwidth=6 toplayer_maxwidth=6 toplayer_prefwidth=6 midlayer1_minwidth=6 midlayer1_maxwidth=6 midlayer1_prefwidth=6 midlayer2_minwidth=6 midlayer2_maxwidth=6 midlayer2_prefwidth=6 midlayer3_minwidth=6 midlayer3_maxwidth=6 midlayer3_prefwidth=6 bottomlayer_minwidth=6 bottomlayer_maxwidth=6 bottomlayer_prefwidth=6 maxuncoupledlength=500
DiffPairsRouting "Schematic Differential Pairs Routing_4" [InNet('TX_AC_SSTin_P')] p6: maxlimit=6 minlimit=6 mostfreqgap=6 toplayer_minwidth=6 toplayer_maxwidth=6 toplayer_prefwidth=6 midlayer1_minwidth=6 midlayer1_maxwidth=6 midlayer1_prefwidth=6 midlayer2_minwidth=6 midlayer2_maxwidth=6 midlayer2_prefwidth=6 midlayer3_minwidth=6 midlayer3_maxwidth=6 midlayer3_prefwidth=6 bottomlayer_minwidth=6 bottomlayer_maxwidth=6 bottomlayer_prefwidth=6 maxuncoupledlength=500
DiffPairsRouting "Schematic Differential Pairs Routing_2" [InNet('TX_AC_WL_CLK_P')] p7: maxlimit=10 minlimit=10 mostfreqgap=10 toplayer_minwidth=15 toplayer_maxwidth=15 toplayer_prefwidth=15 midlayer1_minwidth=15 midlayer1_maxwidth=15 midlayer1_prefwidth=15 midlayer2_minwidth=15 midlayer2_maxwidth=15 midlayer2_prefwidth=15 midlayer3_minwidth=15 midlayer3_maxwidth=15 midlayer3_prefwidth=15 bottomlayer_minwidth=15 bottomlayer_maxwidth=15 bottomlayer_prefwidth=15 maxuncoupledlength=500
DiffPairsRouting "Schematic Differential Pairs Routing" [InNet('TX_AC_WL_CLK_P')] p8: maxlimit=6 minlimit=6 mostfreqgap=6 toplayer_minwidth=6 toplayer_maxwidth=6 toplayer_prefwidth=6 midlayer1_minwidth=6 midlayer1_maxwidth=6 midlayer1_prefwidth=6 midlayer2_minwidth=6 midlayer2_maxwidth=6 midlayer2_prefwidth=6 midlayer3_minwidth=6 midlayer3_maxwidth=6 midlayer3_prefwidth=6 bottomlayer_minwidth=6 bottomlayer_maxwidth=6 bottomlayer_prefwidth=6 maxuncoupledlength=500
DiffPairsRouting [All] p9: maxlimit=6 minlimit=6 mostfreqgap=6 toplayer_minwidth=6 toplayer_maxwidth=6 toplayer_prefwidth=6 midlayer1_minwidth=6 midlayer1_maxwidth=6 midlayer1_prefwidth=6 midlayer2_minwidth=6 midlayer2_maxwidth=6 midlayer2_prefwidth=6 midlayer3_minwidth=6 midlayer3_maxwidth=6 midlayer3_prefwidth=6 bottomlayer_minwidth=6 bottomlayer_maxwidth=6 bottomlayer_prefwidth=6 maxuncoupledlength=500
PlaneClearance [All] p1: clearance=20
PlaneConnect [All] p1: planeconnectstyle=Relief reliefexpansion=20 reliefentries=4 reliefconductorwidth=10 reliefairgap=10
PolygonConnect [All vs InNet('Vped1')] p1: connectstyle=Relief reliefconductorwidth=10 reliefentries=4 polygonreliefangle="90 Angle" airgapwidth=10
RoutingVias [All] p1: holewidth=8 width=18 viastyle="Through Hole" minholewidth=8 minwidth=18 maxholewidth=8 maxwidth=18
SMDNeckDown [All] p1: percent=50.000
SolderMaskExpansion [All] p1: expansion=4
Width [All] p1: maxlimit=6 minlimit=6 preferedwidth=6
27 further rules are at their usual default settings.

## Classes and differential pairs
component class Daughtercard_Input_Output: J1 J2
net class DO_[1..16]: DO_1 DO_2 DO_3 DO_4 DO_5 DO_6 DO_7 DO_8 DO_9 DO_10 DO_11 DO_12 DO_13 DO_14 DO_15 DO_16
component class TargetX_D: Bf_D C1D C2D C3D C4D C5D C6D C7D C8D C9D C10D C11D C12D C13D C14D CDisD CN_D CP_D Cramp_D D1 D2 D3 D4 D5 DONED ISELD MON_TimingD R1_D R1D R2_D R2D R3D R4D R5D R6D R7D R8D R9D R10D R11D R12D R13D R14D R15D R16D R_Bf1_D R_BF2_D R_Trig_D RampMOND RsstD UD VadjND VadjPD VdisD VrampD
component class TargetX_C: Bf_C C1 C2 C2C C3 C4 C4C C5 C6C C9C C10C C11C C12C C13C C14C CDisC CN_C CP_C Cramp_C DONEC ISELC MON_TimingC R1_C R1C R2_C R2C R3C R4C R5C R6C R7C R8C R9C R10C R11C R12C R13C R14C R15C R16C R_BF1_C R_BF2_C R_Trig_C RampMONC RsstC UC VadjNC VadjPC VdisC VrampC
component class TargetX_B: B1 B2 B3 B4 B5 Bf_B C2B C3B C4B C5B C6B C7B C8B C9B C10B C11B C12B C13B C14B CDisB CN_B CP_B Cr_B DONEB ISELB MON_TimEB R1_B R1B R2_B R2B R3B R4B R5B R6B R7B R8B R9B R10B R11B R12B R13B R14B R15B R16B R_BF1_B R_BF2_B R_Trig_B RampMONB RwB UB VadjNB VadjPB VdisB VrB
component class TargetX_A: A1 A2 A3 A4 A5 Bf_A C1A C2A C3A C4A C5A C6A C7A C8A C9A C11A C12A C13A C14A CDisA CN_A CP_A Cr_A DONEA ISELA MON_TimingA R1_A R1A R2_A R2A R3A R4A R5A R6A R7A R8A R9A R10A R11A R12A R13A R14A R15A R16A R_BF1_A R_BF2_A R_Trig_A RampMONA RwA UA VadjN_A VadjP_A VdisA VrA
differential pair TX_BD_WL_CLK: +TX_BD_WL_CLK_P -TX_BD_WL_CLK_N
differential pair TX_BD_SSTin: +TX_BD_SSTin_P -TX_BD_SSTin_N
differential pair TX_AC_WL_CLK: +TX_AC_WL_CLK_P -TX_AC_WL_CLK_N
differential pair TX_AC_SSTin: +TX_AC_SSTin_P -TX_AC_SSTin_N

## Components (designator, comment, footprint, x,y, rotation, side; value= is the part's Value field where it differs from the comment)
A1 "MOSFET" SOT-723 447,2373 r90 top
A2 "MOSFET" SOT-723 521.75,2373 r90 top
A3 "MOSFET" SOT-723 596.5,2373 r90 top
A4 "MOSFET" SOT-723 671.25,2373 r90 top
A5 "MOSFET" SOT-723 746,2373 r90 top
B1 "MOSFET" SOT-723 1220,2378 r90 top
B2 "MOSFET" SOT-723 1293.5,2378 r90 top
B3 "MOSFET" SOT-723 1440.5,2378 r90 top
B4 "MOSFET" SOT-723 1367,2378 r90 top
B5 "MOSFET" SOT-723 1514,2378 r90 top
Bf_A "LT1797CS5" TSOT23-5 178.86,818.86 r315 top
Bf_B "LT1797CS5" TSOT23-5 1921.14,821.14 r225 top
Bf_C "LT1797CS5" TSOT23-5 178.86,818.86 r315 bottom
Bf_D "LT1797CS5" TSOT23-5 1921.14,821.14 r225 bottom
C1 "MOSFET" SOT-723 746,2368.82 r270 bottom
C1A "100nF" CC0402N1R 1020,1100 r90 top
C1B "100nF" CC0402N1R 927,2083 r180 top
C1D "100nF" CC0402N1R 950,1545 r270 bottom
C2 "MOSFET" SOT-723 671.25,2368.82 r270 bottom
C2A "100nF" CC0402N1R 995,1293 r180 top
C2B "100nF" CC0402N1R 1108,1794 r180 top
C2C "100nF" CC0402N1R 1349.33,1720 r180 bottom
C2D "100nF" CC0402N1R 1752,2461 r0 bottom
C3 "MOSFET" SOT-723 596.5,2368.5 r270 bottom
C3A "100nF" CC0402N1R 1016,1343 r90 top
C3B "100nF" CC0402N1R 1108,1854.82 r180 top
C3D "100nF" CC0402N1R 183.12,2061 r0 bottom
C4 "MOSFET" SOT-723 521.75,2369 r270 bottom
C4A "100nF" CC0402N1R 145,1372 r90 top
C4B "100nF" CC0402N1R 1108,1915.64 r180 top
C4C "100nF" CC0402N1R 206,1622 r0 bottom
C4D "100nF" CC0402N1R 1752.12,2406.16 r0 bottom
C5 "MOSFET" SOT-723 447,2369 r270 bottom
C5A "100nF" CC0402N1R 927,2146.6 r180 top
C5B "100nF" CC0402N1R 1108,1976.45 r180 top
C5D "100nF" CC0402N1R 1753.33,2357 r0 bottom
C6A "100nF" CC0402N1R 927,2210.2 r180 top
C6B "100nF" CC0402N1R 1108,2037.27 r180 top
C6C "100nF" CC0402N1R 399,1774 r270 bottom
C6D "100nF" CC0402N1R 1753.33,2304.18 r0 bottom
C7A "100nF" CC0402N1R 927,2273.8 r180 top
C7B "100nF" CC0402N1R 1108,2098.09 r180 top
C7D "100nF" CC0402N1R 1753.33,2252.71 r0 bottom
C8A "100nF" CC0402N1R 927,2337.4 r180 top
C8B "100nF" CC0402N1R 1108,2158.91 r180 top
C8D "100nF" CC0402N1R 1751.54,2200.53 r0 bottom
C9A "100nF" CC0402N1R 1718,1700 r0 top
C9B "100nF" CC0402N1R 1108,2219.73 r180 top
C9C "100nF" CC0402N1R 170.33,1958 r0 bottom
C9D "100nF" CC0402N1R 1751.54,2147.69 r0 bottom
C10A "100nF" CC0402N1R 927,2401 r180 top
C10B "100nF" CC0402N1R 1108,2280.54 r180 top
C10C "100nF" CC0402N1R 170.33,1902.56 r0 bottom
C10D "100nF" CC0402N1R 183.12,2360.21 r0 bottom
C11A "100nF" CC0402N1R 298,854 r135 top
C11B "100nF" CC0402N1R 1108,2341.36 r180 top
C11C "100nF" CC0402N1R 1435.33,2015.67 r270 bottom
C11D "100nF" CC0402N1R 183.12,2300.37 r0 bottom
C12A "100nF" CC0402N1R 660,1882 r0 top
C12B "100nF" CC0402N1R 1626,1869 r0 top
C12C "100nF" CC0402N1R 1379.89,2015.67 r270 bottom
C12D "100nF" CC0402N1R 183.12,2240.53 r0 bottom
C13A "100nF" CC0402N1R 782,1620 r0 top
C13B "100nF" CC0402N1R 1108,2402.18 r180 top
C13C "100nF" CC0402N1R 1324.44,2015.67 r270 bottom
C13D "100nF" CC0402N1R 183.12,2180.68 r0 bottom
C14A "100nF" CC0402N1R 249,1545 r270 top
C14B "100nF" CC0402N1R 1108,2463 r180 top
C14C "100nF" CC0402N1R 1269,2015.67 r270 bottom
C14D "100nF" CC0402N1R 183.12,2120.84 r0 bottom
CDisA "10uF" CC0402N1R 170,1307 r0 top
CDisB "10uF" CC0402N1R 1129,1351 r270 top
CDisC "10uF" CC0402N1R 1010,1312.67 r270 bottom
CDisD "10uF" CC0402N1R 2007,1511 r270 bottom
CN_A "1uF" CC0402N1R 132,1070.67 r90 top
CN_B "1uF" CC0402N1R 999,912 r0 top
CN_C "1uF" CC0402N1R 1091.33,913 r180 bottom
CN_D "1uF" CC0402N1R 1923,1109 r90 bottom
CP_A "1uF" CC0402N1R 77,994 r90 top
CP_B "1uF" CC0402N1R 1091.67,913 r180 top
CP_C "1uF" CC0402N1R 999,912 r0 bottom
CP_D "1uF" CC0402N1R 1927,1037 r90 bottom
Cr_A "200pF" CC0402N1R 134.67,1212 r0 top
Cr_B "200pF" CC0402N1R 1141,1191.33 r90 top
Cramp_C "200pF" CC0402N1R 996,1152.67 r90 bottom
Cramp_D "200pF" CC0402N1R 1992.33,1247 r180 bottom
D1 "MOSFET" SOT-723 1514,2378 r270 bottom
D2 "MOSFET" SOT-723 1441,2378.5 r270 bottom
D3 "MOSFET" SOT-723 1368,2378 r270 bottom
D4 "MOSFET" SOT-723 1294,2378 r270 bottom
D5 "MOSFET" SOT-723 1220,2378 r270 bottom
DONEA "SP1.5S" SP1.5SQ 389,1659 r0 top
DONEB "SP1.5S" SP1.5SQ 1318,1619 r0 top
DONEC "SP1.5S" SP1.5SQ 977,1710 r180 bottom
DONED "" SP1.5SQ 1869,1740 r180 bottom
ISELA "SP1.5S" SP1.5SQ 203,1234 r0 top
ISELB "SP1.5S" SP1.5SQ 1145,1258 r180 top
ISELC "SP1.5S" SP1.5SQ 1006,1229 r270 bottom
ISELD "" SP1.5SQ 1911,1664 r180 bottom
J1 "SPD08 Card Edge Connector Mating Card Layout" "Card Edge Male"#1 368.58,99.88 r0 top
J2 "SPD08 Card Edge Connector Mating Card Layout" "Card Edge Male"#2 370.1,3185.88 r0 top
MON_TimEB "SP1.5S" SP1.5SQ 1139,1117 r90 top
MON_TimingA "SP1.5S" SP1.5SQ 166,1157 r270 top
MON_TimingC "SP1.5S" SP1.5SQ 1032,1063 r135 bottom
MON_TimingD "SP1.5S" SP1.5SQ 1937,1868 r180 bottom
R1_A "4.7k" RC0603N1R 600,1794 r270 top
R1_B "4.7k" RC0603N1R 1566,1785 r270 top
R1_C "4.7k" RC0603N1R 599,1795 r270 bottom
R1_D "4.7k" RC0603N1R 1501,1677.5 r270 bottom
R1A "1k" RC0402N1R 377.95,715 r90 top
R1B "1k" RC0402N1R 1104.82,710 r90 top
R1C "1k" RC0402N1R 988.35,530 r90 bottom
R1D "1k" RC0402N1R 1761.23,530 r90 bottom
R2_A "4.7k" RC0603N1R 97,1438 r0 top
R2_B "4.7k" RC0603N1R 1142,1523 r270 top
R2_C "4.7k" RC0603N1R 1006,1425 r180 bottom
R2_D "4.7k" RC0603N1R 1955,1555 r270 bottom
R2A "1k" RC0402N1R 383.86,530 r90 top
R2B "1k" RC0402N1R 1118.35,530 r90 top
R2C "1k" RC0402N1R 1013.96,715 r90 bottom
R2D "1k" RC0402N1R 1740.83,710 r90 bottom
R3A "1k" RC0402N1R 468.81,715 r90 top
R3B "1k" RC0402N1R 1195.68,710 r90 top
R3C "1k" RC0402N1R 905.67,530 r90 bottom
R3D "1k" RC0402N1R 1668.35,530 r90 bottom
R4A "1K" RC0402N1R 470.47,530 r90 top
R4B "1K" RC0402N1R 1208.35,530 r90 top
R4C "1K" RC0402N1R 923.1,715 r90 bottom
R4D "1K" RC0402N1R 1649.97,710 r90 bottom
R5A "1K" RC0402N1R 559.67,715 r90 top
R5B "1K" RC0402N1R 1286.53,710 r90 top
R5C "1K" RC0402N1R 822.99,530 r90 bottom
R5D "1K" RC0402N1R 1578.35,530 r90 bottom
R6A "1K" RC0402N1R 559.21,530 r90 top
R6B "1K" RC0402N1R 1298.35,530 r90 top
R6C "1K" RC0402N1R 832.24,715 r90 bottom
R6D "1K" RC0402N1R 1559.11,710 r90 bottom
R7A "1K" RC0402N1R 650.53,715 r90 top
R7B "1K" RC0402N1R 1377.39,710 r90 top
R7C "1K" RC0402N1R 736.38,530 r90 bottom
R7D "1K" RC0402N1R 1488.35,530 r90 bottom
R8A "1K" RC0402N1R 645.83,530 r90 top
R8B "1K" RC0402N1R 1398.35,530 r90 top
R8C "1K" RC0402N1R 741.39,715 r90 bottom
R8D "1K" RC0402N1R 1468.25,710 r90 bottom
R9A "1K" RC0402N1R 741.39,715 r90 top
R9B "1K" RC0402N1R 1468.25,710 r90 top
R9C "1K" RC0402N1R 645.83,530 r90 bottom
R9D "1K" RC0402N1R 1398.35,530 r90 bottom
R10A "1K" RC0402N1R 736.38,530 r90 top
R10B "1K" RC0402N1R 1488.35,530 r90 top
R10C "1K" RC0402N1R 650.53,715 r90 bottom
R10D "1K" RC0402N1R 1377.39,710 r90 bottom
R11A "1K" RC0402N1R 832.24,715 r90 top
R11B "1K" RC0402N1R 1559.11,710 r90 top
R11C "1K" RC0402N1R 559.21,530 r90 bottom
R11D "1K" RC0402N1R 1298.35,530 r90 bottom
R12A "1K" RC0402N1R 822.99,530 r90 top
R12B "1K" RC0402N1R 1578.35,530 r90 top
R12C "1K" RC0402N1R 559.67,715 r90 bottom
R12D "1K" RC0402N1R 1286.53,710 r90 bottom
R13A "1K" RC0402N1R 923.1,715 r90 top
R13B "1K" RC0402N1R 1649.97,710 r90 top
R13C "1K" RC0402N1R 470.47,530 r90 bottom
R13D "1K" RC0402N1R 1208.35,530 r90 bottom
R14A "1K" RC0402N1R 905.67,530 r90 top
R14B "1K" RC0402N1R 1668.35,530 r90 top
R14C "1K" RC0402N1R 468.81,715 r90 bottom
R14D "1K" RC0402N1R 1195.68,710 r90 bottom
R15A "1K" RC0402N1R 990,530 r90 top
R15B "1K" RC0402N1R 1740.83,710 r90 top
R15C "1K" RC0402N1R 383.86,530 r90 bottom
R15D "1K" RC0402N1R 1118.35,530 r90 bottom
R16A "1K" RC0402N1R 1013.96,715 r90 top
R16B "1K" RC0402N1R 1761.23,530 r90 top
R16C "1K" RC0402N1R 377.95,715 r90 bottom
R16D "1K" RC0402N1R 1104.82,710 r90 bottom
R_BF1_A "1.3K" RC0402N1R 100,760 r315 top
R_BF1_B "1.3K" RC0402N1R 1839.49,732.78 r315 top
R_BF1_C "1.3K" RC0402N1R 100,760 r315 bottom
R_BF1_D "1.3K" RC0402N1R 1839.49,732.78 r135 bottom
R_BF2_A "2K" RC0402N1R 134.69,944.69 r225 top
R_BF2_B "2K" RC0402N1R 1990,940 r135 top
R_BF2_C "2K" RC0402N1R 134.69,944.69 r45 bottom
R_BF2_D "2K" RC0402N1R 1990,940 r315 bottom
R_Trig_A "100R" RC0805N1R 596,2606 r90 top
R_Trig_B "100R" RC0805N1R 1367,2489 r90 top
R_Trig_C "100R" RC0805N1R 596,2247.63 r270 bottom
R_Trig_D "100R" RC0805N1R 1368,2243.63 r270 bottom
RampMONA "SP1.5S" SP1.5SQ 74,1320 r270 top
RampMONB "SP1.5S" SP1.5SQ 1079,1316 r90 top
RampMONC "SP1.5S" SP1.5SQ 1087,1284 r90 bottom
RampMOND "" SP1.5SQ 1986,1944 r180 bottom
RsstC "100R" RC0402N1R 139,1762 r0 bottom
RsstD "100R" RC0402N1R 1154,2592 r0 bottom
RwA "100R" RC0402N1R 244,1838 r0 top
RwB "100R" RC0402N1R 1966,1839 r180 top
SHoutB "" SP1.5SQ 2003,1041 r270 top
UA "TargetX" TQFP128_MZA 595.12,1241.97 r90 top
UB "TargetX" TQFP128_MZA 1540.43,1241.97 r90 top
UC "TargetX" TQFP128_MZA 595.12,1241.97 r90 bottom
UD "TargetX" TQFP128_MZA 1540.43,1241.97 r90 bottom
VadjN_A "SP1.5S" SP1.5SQ 68,1147 r90 top
VadjNB "SP1.5S" SP1.5SQ 1004,851 r0 top
VadjNC "SP1.5S" SP1.5SQ 1078,851 r180 bottom
VadjND "" SP1.5SQ 1986,1112 r90 bottom
VadjP_A "SP1.5S" SP1.5SQ 68,1075 r90 top
VadjPB "SP1.5S" SP1.5SQ 1078,851 r180 top
VadjPC "SP1.5S" SP1.5SQ 1004,851 r180 bottom
VadjPD "" SP1.5SQ 2004,1041 r90 bottom
VdisA "SP1.5S" SP1.5SQ 111,1319 r270 top
VdisB "SP1.5S" SP1.5SQ 1049,1667 r90 top
VdisC "SP1.5S" SP1.5SQ 1048,1314 r90 bottom
VdisD "SP1.5S" SP1.5SQ 2003,1598 r90 bottom
VrA "SP1.5S" SP1.5SQ 65,1217 r270 top
VrampC "SP1.5S" SP1.5SQ 1033,1163 r270 bottom
VrampD "SP1.5S" SP1.5SQ 2015,1311 r90 bottom
VrB "SP1.5S" SP1.5SQ 1090,1256 r90 top

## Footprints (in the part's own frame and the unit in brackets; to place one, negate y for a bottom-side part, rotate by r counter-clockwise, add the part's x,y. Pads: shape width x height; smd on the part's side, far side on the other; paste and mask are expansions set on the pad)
"Card Edge Male"#1 [mm]
  rect 0.55x2.6 smd: 1(0,0.003) 3(0.8,0.003) 5(1.6,0.003) 7(2.4,0.003) 9(3.2,0.003) 11(4,0.003) 13(4.8,0.003) 15(5.6,0.003) 17(6.4,0.003) 19(7.2,0.003) 21(8,0.003) 23(8.8,0.003) 25(9.6,0.003) 27(10.4,0.003) 29(11.2,0.003) 31(12,0.003) 33(12.8,0.003) 35(13.6,0.003) 37(14.4,0.003) 39(15.2,0.003) 41(16,0.003) 43(16.8,0.003) 45(20.8,0.003) 47(21.6,0.003) 49(22.4,0.003) 51(23.2,0.003) 53(24,0.003) 55(24.8,0.003) 57(25.6,0.003) 59(26.4,0.003) 61(27.2,0.003) 63(28,0.003) 65(28.8,0.003) 67(29.6,0.003) 69(30.4,0.003) 71(31.204,0.003) 73(32,0.003) 75(32.802,0.003) 77(33.598,0.003) 79(34.4,0.003)
  rect 0.55x2.6 smd far side: 2(0,0.003) 4(0.8,0.003) 6(1.6,0.003) 8(2.4,0.003) 10(3.2,0.003) 12(4,0.003) 14(4.8,0.003) 16(5.6,0.003) 18(6.4,0.003) 20(7.2,0.003) 22(8,0.003) 24(8.8,0.003) 26(9.6,0.003) 28(10.4,0.003) 30(11.2,0.003) 32(12,0.003) 34(12.8,0.003) 36(13.6,0.003) 38(14.4,0.003) 40(15.2,0.003) 42(16,0.003) 44(16.8,0.003) 46(20.8,0.003) 48(21.6,0.003) 50(22.4,0.003) 52(23.2,0.003) 54(24,0.003) 56(24.8,0.003) 58(25.6,0.003) 60(26.4,0.003) 62(27.2,0.003) 64(28,0.003) 66(28.8,0.003) 68(29.6,0.003) 70(30.4,0.003) 72(31.2,0.003) 74(32,0.003) 76(32.8,0.003) 78(33.6,0.003) 80(34.4,0.003)
"Card Edge Male"#2 [mm]
  rect 0.55x2.6 smd far side: 1(0,0.003) 3(0.8,0.003) 5(1.6,0.003) 7(2.4,0.003) 9(3.2,0.003) 11(4,0.003) 13(4.8,0.003) 15(5.6,0.003) 17(6.4,0.003) 19(7.2,0.003) 21(8,0.003) 23(8.8,0.003) 25(9.6,0.003) 27(10.4,0.003) 29(11.2,0.003) 31(12,0.003) 33(12.8,0.003) 35(13.6,0.003) 37(14.4,0.003) 39(15.2,0.003) 41(16,0.003) 43(16.8,0.003) 45(20.8,0.003) 47(21.6,0.003) 49(22.4,0.003) 51(23.2,0.003) 53(24,0.003) 55(24.8,0.003) 57(25.6,0.003) 59(26.4,0.003) 61(27.2,0.003) 63(28,0.003) 65(28.8,0.003) 67(29.6,0.003) 69(30.4,0.003) 71(31.204,0.003) 73(32,0.003) 75(32.802,0.003) 77(33.598,0.003) 79(34.4,0.003)
  rect 0.55x2.6 smd: 2(0,0.003) 4(0.8,0.003) 6(1.6,0.003) 8(2.4,0.003) 10(3.2,0.003) 12(4,0.003) 14(4.8,0.003) 16(5.6,0.003) 18(6.4,0.003) 20(7.2,0.003) 22(8,0.003) 24(8.8,0.003) 26(9.6,0.003) 28(10.4,0.003) 30(11.2,0.003) 32(12,0.003) 34(12.8,0.003) 36(13.6,0.003) 38(14.4,0.003) 40(15.2,0.003) 42(16,0.003) 44(16.8,0.003) 46(20.8,0.003) 48(21.6,0.003) 50(22.4,0.003) 52(23.2,0.003) 54(24,0.003) 56(24.8,0.003) 58(25.6,0.003) 60(26.4,0.003) 62(27.2,0.003) 64(28,0.003) 66(28.8,0.003) 68(29.6,0.003) 70(30.4,0.003) 72(31.2,0.003) 74(32,0.003) 76(32.8,0.003) 78(33.6,0.003) 80(34.4,0.003)
CC0402N1R [mm] "Chip capacitor 0402 ROUND pad"
  rrect30% 0.55x0.65 smd mask+0.025: 1(-0.525,0) 2(0.525,0)
  silkscreen extent 0,-0.25 0,0.25, body extent -0.51,-0.25 0.51,0.25, height 0.5
RC0402N1R [mm] "Chip capacitor 0402 ROUNDED PAD"
  rrect50% 0.6x0.65 smd: 1(-0.55,0) 2(0.55,0)
  silkscreen extent 0,-0.25 0,0.25, body extent -0.51,-0.25 0.51,0.25, height 0.36
RC0603N1R [mm] "Chip resistor 0603 ROUNDED PAD"
  rrect50% 0.75x0.85 smd: 1(-0.8,0) 2(0.8,0)
  silkscreen extent -0.2,-0.38 0.2,0.38, body extent -0.8,-0.4 0.8,0.4, height 0.46
RC0805N1R [mm] "Chip resistor 0805 ROUNDED PAD"
  rrect50% 0.9x1.35 smd: 1(-1,0) 2(1,0)
  silkscreen extent -0.3,-0.64 0.3,0.64, body extent -1.02,-0.63 1.02,0.63, height 0.51
SOT-723 [mm]
  rect 0.32x0.17 smd: 1(-0.563,0.381) 2(-0.571,-0.381)
  rect 0.32x0.16 smd: 3(0.508,0)
  silkscreen extent -0.24,-0.89 0.57,0.89, body extent -0.57,-0.63 1.28,0.64, height 1.02
SP1.5SQ [mil] "Solder Pad 1.5mm SMT"
  rrect20% 50x30 smd: 1(0,0)
TQFP128_MZA [mil]
  oval 65x8 smd mask+2: 1(-302.5,243.35) 2(-302.5,227.65) 3(-302.5,211.95) 4(-302.5,196.25) 5(-302.5,180.55) 6(-302.5,164.85) 7(-302.5,149.15) 8(-302.5,133.45) 9(-302.5,117.75) 10(-302.5,102.05) 11(-302.5,86.35) 12(-302.5,70.65) 13(-302.5,54.95) 14(-302.5,39.25) 15(-302.5,23.55) 16(-302.5,7.85) 17(-302.5,-7.85) 18(-302.5,-23.55) 19(-302.5,-39.25) 20(-302.5,-54.95) 21(-302.5,-70.65) 22(-302.5,-86.35) 23(-302.5,-102.05) 24(-302.5,-117.75) 25(-302.5,-133.45) 26(-302.5,-149.15) 27(-302.5,-164.85) 28(-302.5,-180.55) 29(-302.5,-196.25) 30(-302.5,-211.95) 31(-302.5,-227.65) 32(-302.5,-243.35) 65(302.5,-243.35) 66(302.5,-227.65) 67(302.5,-211.95) 68(302.5,-196.25) 69(302.5,-180.55) 70(302.5,-164.85) 71(302.5,-149.15) 72(302.5,-133.45) 73(302.5,-117.75) 74(302.5,-102.05) 75(302.5,-86.35) 76(302.5,-70.65) 77(302.5,-54.95) 78(302.5,-39.25) 79(302.5,-23.55) 80(302.5,-7.85) 81(302.5,7.85) 82(302.5,23.55) 83(302.5,39.25) 84(302.5,54.95) 85(302.5,70.65) 86(302.5,86.35) 87(302.5,102.05) 88(302.5,117.75) 89(302.5,133.45) 90(302.5,149.15) 91(302.5,164.85) 92(302.5,180.55) 93(302.5,196.25) 94(302.5,211.95) 95(302.5,227.65) 96(302.5,243.35)
  oval 8x65 smd mask+2: 33(-243.35,-302.5) 34(-227.65,-302.5) 35(-211.95,-302.5) 36(-196.25,-302.5) 37(-180.55,-302.5) 38(-164.85,-302.5) 39(-149.15,-302.5) 40(-133.45,-302.5) 41(-117.75,-302.5) 42(-102.05,-302.5) 43(-86.35,-302.5) 44(-70.65,-302.5) 45(-54.95,-302.5) 46(-39.25,-302.5) 47(-23.55,-302.5) 48(-7.85,-302.5) 49(7.85,-302.5) 50(23.55,-302.5) 51(39.25,-302.5) 52(54.95,-302.5) 53(70.65,-302.5) 54(86.35,-302.5) 55(102.05,-302.5) 56(117.75,-302.5) 57(133.45,-302.5) 58(149.15,-302.5) 59(164.85,-302.5) 60(180.55,-302.5) 61(196.25,-302.5) 62(211.95,-302.5) 63(227.65,-302.5) 64(243.35,-302.5) 97(243.35,302.5) 98(227.65,302.5) 99(211.95,302.5) 100(196.25,302.5) 101(180.55,302.5) 102(164.85,302.5) 103(149.15,302.5) 104(133.45,302.5) 105(117.75,302.5) 106(102.05,302.5) 107(86.35,302.5) 108(70.65,302.5) 109(54.95,302.5) 110(39.25,302.5) 111(23.55,302.5) 112(7.85,302.5) 113(-7.85,302.5) 114(-23.55,302.5) 115(-39.25,302.5) 116(-54.95,302.5) 117(-70.65,302.5) 118(-86.35,302.5) 119(-102.05,302.5) 120(-117.75,302.5) 121(-133.45,302.5) 122(-149.15,302.5) 123(-164.85,302.5) 124(-180.55,302.5) 125(-196.25,302.5) 126(-211.95,302.5) 127(-227.65,302.5) 128(-243.35,302.5)
  silkscreen extent -330,-330 330,330, body extent -295,-295 295,295, height 48
TSOT23-5 [mm] "5-LEAD plastic"
  oval 1.22x0.6 smd mask+0.051: 1(-1.31,0.95) 2(-1.31,0) 3(-1.31,-0.95) 4(1.31,-0.95) 5(1.31,0.95)
  silkscreen extent -1.4,-1.68 0.98,1.78, body extent -1.29,-1.45 1.29,1.45, height 1.46

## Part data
A1 A2 A3 A4 A5 B1 B2 B3 B4 B5 C1 C2 C3 C4 C5 D1 D2 D3 D4 D5: library part RUM001L02, "N-Channel 20V 100mA (Ta) 150mW (Ta) Surface Mount VMT3"
Bf_A Bf_B Bf_C Bf_D: library part LT1797CS5#TRMPBF, "Buffer Op-Amp"
C1A C1B C1D C2A C2B C2C C2D C3A C3B C3D C4A C4B C4C C4D C5A C5B C5D C6A C6B C6C C6D C7A C7B C7D C8A C8B C8D C9A C9B C9C C9D C10A C10B C10C C10D C11A C11B C11C C11D C12A C12B C12C C12D C13A C13B C13C C13D C14A C14B C14C C14D: library part CAPCC0402_100N_50VX7R, "0.10µF 50V Ceramic Capacitor X7R 0402", Manufacturer=TDK, Manufacturer No=C1005X7R1H104K050BB, Package="Cap Chip 0402", Supplier Part Number 1=445-5932-1-ND, Voltage rating=50V
CDisA CDisB CDisC CDisD CN_A CN_B CN_C CN_D CP_A CP_B CP_C CP_D: library part CAPCC0402_1.0U_50VX7R, "1µF 6.3V Ceramic Capacitor X7R 0402", Manufacturer=TDK, Manufacturer No=GRM155R70J105KA12D, Package="Cap Chip 0402", Supplier Part Number 1=490-10024-1-ND, Voltage rating=6.3V
Cr_A Cr_B Cramp_C Cramp_D: library part CAPCC0402_200P_50VNP0, "Capacitor chip ceramic 0402 50V NPO", Manufacturer=Murata, Manufacturer No=GRM1555C1H201JA01D, Package="Cap Chip 0402", Supplier Part Number 1=490-3232-1-ND, Voltage rating=50V
DONEA DONEB DONEC ISELA ISELB ISELC MON_TimEB MON_TimingA MON_TimingC MON_TimingD RampMONA RampMONB RampMONC VadjN_A VadjNB VadjNC VadjP_A VadjPB VadjPC VdisA VdisB VdisC VdisD VrA VrampC VrampD VrB: "Wire solder pin 1.5mm"
DONED ISELD RampMOND SHoutB VadjND VadjPD: library part SP1.5S, "Wire solder pin 1.5mm"
R1_A R1_B R1_C R1_D R2_A R2_B R2_C R2_D: library part RES0603-1-1.00K-1%100PPM, "Chip Resistor 0603 100mW 1% 100ppm", Manufacturer=Yageo, Manufacturer No=RC0603FR-071KL, Package="Res Chip 0603", Supplier Part Number 1=603-RC0603FR-071KL
R1A R1B R1C R1D R2A R2B R2C R2D R3A R3B R3C R3D R4A R4B R4C R4D R5A R5B R5C R5D R6A R6B R6C R6D R7A R7B R7C R7D R8A R8B R8C R8D R9A R9B R9C R9D R10A R10B R10C R10D R11A R11B R11C R11D R12A R12B R12C R12D R13A R13B R13C R13D R14A R14B R14C R14D R15A R15B R15C R15D R16A R16B R16C R16D R_BF1_A R_BF1_B R_BF1_C R_BF1_D R_BF2_A R_BF2_B R_BF2_C R_BF2_D: library part RES0402-0-0R-1%100PPM, "Chip Resistor 0402 62.5mW 1% 100ppm", Manufacturer=Panasonic, Manufacturer No=ERJ-2GE0R00X, Package="Res Chip 0402", Supplier Part Number 1=P0.0JCT-ND
R_Trig_A R_Trig_B R_Trig_C R_Trig_D: library part RES0805, "Chip Resistor 0805", Package="Res Chip 0805"
RsstC RsstD RwA RwB: library part RES0402-100R-1%100PPM, "RES SMD 100 OHM 1% 1/10W 0402", Manufacturer=Panasonic, Manufacturer No=ERJ-2RKF1000X, Package="Res Chip 0402", Supplier Part Number 1=P100LCT-ND
UA UB UC UD: library part DIGITZ_TargetX, "16-channel, 1GSPS Transient Waveform Recorder", Manufacturer=UHM_IDL, Package=TQFP128

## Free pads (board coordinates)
  round 0 on Mech16 paste+0 mask+0: 1(383.38,836.59) 1(383.38,836.59)

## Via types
v1: diameter 18, hole 8, Top Layer to Bottom Layer, 106 vias
v2: diameter 18, hole 8, Top Layer to AUX Route Horz, 56 vias
v3: diameter 15, hole 8, Top Layer to Bottom Layer, 53 vias
v4: diameter 18, hole 8, AUX Route Vert to Bottom Layer, 42 vias
v5: diameter 18, hole 8, AUX Route Horz to Bottom Layer, 40 vias
v6: diameter 18, hole 8, Top Layer to AUX Route Vert, 34 vias
v7: diameter 18, hole 8, Top Layer to GND, 33 vias
v8: diameter 18, hole 8, GND (Plane2) to Bottom Layer, 27 vias
v9: diameter 18, hole 8, AUX Routing (LVDS) to Bottom Layer, 23 vias
v10: diameter 18, hole 8, Top Layer to AUX Routing (LVDS), 22 vias
v11: diameter 15, hole 8, Top Layer to 2.5V, 13 vias
v12: diameter 18, hole 8, Top Layer to 2.5V, 13 vias
v13: diameter 15, hole 8, Top Layer to GND, 10 vias
v14: diameter 18, hole 8, 2.5V to Bottom Layer, 8 vias
v15: diameter 15, hole 8, GND (Plane2) to Bottom Layer, 4 vias
v16: diameter 15, hole 8, Top Layer to AUX Route Horz, 4 vias
v17: diameter 18, hole 8, AUX Route Vert to AUX Route Horz, 4 vias
v18: diameter 15, hole 8, 2.5V to Bottom Layer, 2 vias
v19: diameter 18, hole 8, AUX Routing (LVDS) to AUX Route Vert, 2 vias
v20: diameter 15 (per signal layer), hole 8, Top Layer to GND, 1 vias
v21: diameter 15, hole 8, AUX Routing (LVDS) to Bottom Layer, 1 vias
v22: diameter 15, hole 8, Top Layer to AUX Route Vert, 1 vias
v23: diameter 8, hole 8, Top Layer to AUX Route Horz, 1 vias

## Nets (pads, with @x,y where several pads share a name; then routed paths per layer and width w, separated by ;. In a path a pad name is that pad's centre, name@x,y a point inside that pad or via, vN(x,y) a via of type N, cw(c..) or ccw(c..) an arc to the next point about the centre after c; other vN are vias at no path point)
2.5V: Bf_A.5 Bf_B.5 Bf_C.5 Bf_D.5 C1A.2 C1B.2 C1D.2 C2A.2 C2B.2 C2C.2 C2D.2 C3A.2 C3B.2 C3D.2 C4A.2 C4B.2 C4C.2 C4D.2 C5A.2 C5B.2 C5D.2 C6A.2 C6B.2 C6C.2 C6D.2 C7A.2 C7B.2 C7D.2 C8A.2 C8B.2 C8D.2 C9A.2 C9B.2 C9C.2 C9D.2 C10A.2 C10B.2 C10C.2 C10D.2 C11A.2 C11B.2 C11C.2 C11D.2 C12A.2 C12B.2 C12C.2 C12D.2 C13A.2 C13B.2 C13C.2 C13D.2 C14A.2 C14B.2 C14C.2 C14D.2 J2.15 J2.16 J2.24 J2.35 J2.39 J2.53 J2.61 J2.65 J2.66 J2.71 J2.72 J2.74 J2.79 R2_A.1 R2_B.1 R2_C.1 R2_D.1 R_BF1_A.2 R_BF1_B.2 R_BF1_C.2 R_BF1_D.2 R_Trig_A.2 R_Trig_B.2 R_Trig_C.2 R_Trig_D.2 UA.34 UA.40 UA.52 UA.60 UA.67 UA.77 UA.82 UA.92 UA.97 UA.102 UA.107 UA.115 UA.120 UA.128 UB.34 UB.40 UB.52 UB.60 UB.67 UB.77 UB.82 UB.92 UB.97 UB.102 UB.107 UB.115 UB.120 UB.128 UC.34 UC.40 UC.52 UC.60 UC.67 UC.77 UC.82 UC.92 UC.97 UC.102 UC.107 UC.115 UC.120 UC.128 UD.34 UD.40 UD.52 UD.60 UD.67 UD.77 UD.82 UD.92 UD.97 UD.102 UD.107 UD.115 UD.120 UD.128 | length 15710.2
  Top Layer w6: R2_A.1@65.5,1438 53,1425.5 53,1391 60,1384 v12(69,1384) 77.67,1392.67 C4A.2@145,1392.67 204.87,1332.8 251.3,1332.8 255.78,1328.32 ; R_BF1_A.2@115.31,744.69 129.31,744.69 v14(166,708) 194.16,679.84 258.47,679.84 265,686.36 265,710.95 241.78,734.17 Bf_A.5@241.78,808.84 ; v3(230,1104) 250.22,1124.22 UA.120@292.62,1124.22 ; 256.68,1328.32 UA.107@292.62,1328.32 ; v3(278,742) 278,863.23 C11A.2@283.38,868.62 283.38,896.62 237,943 237,986 249.62,998.62 UA.128@292.62,998.62 ; UA.115@292.62,1202.72 v11@364.72,1202.72 ; UA.102@292.62,1406.82 354.82,1406.82 v3(364,1416) ; UA.97@292.62,1485.32 256.68,1485.32 249,1493 C14A.2@249,1524.33 279.33,1524.33 v1(315,1560) ; UA.92@414.57,1544.47 414.57,1474.43 v12(419,1470) ; v3(479,2925) 479,2928 590.57,3039.57 J2.16@590.57,3186 ; UA.82@571.57,1544.47 571.57,1914 v10(573,1914) 648.67,1914 C12A.2@680.67,1882 680.67,1860.67 650.07,1830.07 UA.77@650.07,1544.47 ; R_Trig_A.2@596,2641 R_Trig_A.2@596,2645.37 v12(596,2699) ; J2.24@716.56,3186 716.56,3056.44 v12(717,3056) ; C13A.2@802.67,1620 807.07,1615.6 UA.67@807.07,1544.47 ; UA.40@897.62,1108.52 1007.85,1108.52 C1A.2@1020,1120.67 1031.33,1132 1077,1132 1077,1130 1089,1118 1089,1090 1114,1065 1137.75,1065 1145.75,1073 1151.63,1073 1167,1088.37 1167,1103 1189,1125 1189.78,1124.22 UB.120@1237.93,1124.22 ; UA.52@897.62,1296.92 C2A.2@970.41,1296.92 ; UA.60@897.62,1422.52 970.15,1422.52 ; UA.34@897.94,1014 UA.34@897.62,1014.32 936.68,1014.32 ; C1B.2@906.33,2083 902,2083 v11(864,2121) 889.6,2146.6 C5A.2@906.33,2146.6 ; C6A.2@906.33,2210.2 899.8,2210.2 v11(864,2246) 891.8,2273.8 C7A.2@906.33,2273.8 ; C8A.2@906.33,2337.4 897.6,2337.4 v11(864,2371) 894,2401 C10A.2@906.33,2401 ; 936.98,1014.02 v14(967,984) ; 970.45,1422.22 1016,1376.67 C3A.2@1016,1363.67 v12@1056.33,1363.67 ; C2A.2@974.33,1293 1009.33,1258 v12(1024,1258) ; v11(999,2156) v11@1001.91,2158.91 ; C2B.2@1087.33,1794 1034,1794 v11(999,1829) 1024.82,1854.82 C3B.2@1087.33,1854.82 ; C4B.2@1087.33,1915.64 1033.9,1915.64 v11(999.33,1950.2) 1025.59,1976.45 C5B.2@1087.33,1976.45 ; C6B.2@1087.33,2037.27 1034.46,2037.27 v11(999.33,2072.4) 1025.02,2098.09 C7B.2@1087.33,2098.09 ; C8B.2@1087.33,2158.91 v11@1001.91,2158.91 ; C9B.2@1087.33,2219.73 1062.73,2219.73 v11@1001.91,2158.91 ; C10B.2@1087.33,2280.54 1035.59,2280.54 v11(999.33,2316.8) 1023.9,2341.36 C11B.2@1087.33,2341.36 ; C13B.2@1087.33,2402.18 1033.82,2402.18 v11(999,2437) 1025,2463 C14B.2@1087.33,2463 ; R2_B.1@1142,1554.5 1223.5,1554.5 v3(1253,1525) 1264,1525 1279,1510 1279,1489 1275.32,1485.32 UB.97@1237.93,1485.32 ; v3(1193,895) 1192,896 1192,992 1198.62,998.62 UB.128@1237.93,998.62 ; UB.115@1237.93,1202.72 1326.72,1202.72 v12(1327,1203) ; UB.107@1237.93,1328.32 v11@1309.68,1328.32 ; UB.102@1237.93,1406.82 v11@1314.82,1406.82 ; v11@1315.12,1407.12 v11(1320,1412) ; v3(1333,1779) 1359.88,1752.12 UB.92@1359.88,1544.47 ; R_Trig_B.2@1367,2528.37 v12(1367,2576) ; v14(1473,3040) 1503.96,3070.96 J2.66@1503.96,3186 ; UB.82@1516.88,1544.47 1516.88,1872.88 v1(1543,1899) 1635,1899 1646.67,1887.33 C12B.2@1646.67,1869 ; 1595.08,1595.62 1595.08,1595.92 1589,1602 1589,1652 1595.73,1658.73 1595.73,1766.73 1607,1778 1607,1812.11 1646.67,1851.78 C12B.2@1646.67,1869 ; UB.77@1595.38,1544.47 1595.38,1595.62 ; J2.72@1598.45,3186 1598.45,3108.55 1606,3101 v12(1614,3101) 1622,3101 1629.94,3108.95 J2.74@1629.94,3186 ; C12B.2@1645.73,1869 C12B.2@1646.67,1869 ; C9A.2@1738.67,1700 1752.38,1686.29 UB.67@1752.38,1544.47 ; v11@1783.48,1422.52 UB.60@1842.93,1422.52 ; UB.34@1842.93,1014.32 1875.68,1014.32 v1(1895,995) ; UB.40@1842.93,1108.52 2000.52,1108.52 v12(2020,1128) ; UB.52@1842.93,1296.92 1879.77,1296.92 1897.69,1279 1932,1279 v3(1945,1292) ; R_BF1_B.2@1854.8,717.47 1870.37,717.47 Bf_B.5@1911.11,758.22 1902.33,767 v1(1868,767)
  Bottom Layer w6: R_BF1_C.2@115.31,744.69 150,779.38 165.46,779.38 Bf_C.5@188.89,755.95 ; v14(166,708) 166,733.06 Bf_C.5@188.89,755.95 ; Bf_C.5@176.62,755.95 Bf_C.5@188.89,755.95 ; C10C.2@191,1902.56 201.56,1892 v3(273,1892) ; C9C.2@191,1958 208,1941 v3(273,1941) ; C3D.2@203.79,2061 241,2061 255.5,2075.5 v3(270,2090) 239.16,2120.84 C14D.2@203.79,2120.84 ; C13D.2@203.79,2180.68 240.68,2180.68 v3(270,2210) 239.47,2240.53 C12D.2@203.79,2240.53 ; C11D.2@203.79,2300.37 240.37,2300.37 v3(270,2330) 239.79,2360.21 C10D.2@203.79,2360.21 ; v3(230,1104) 234.52,1108.52 UC.40@292.62,1108.52 ; 237,943 237,1002 249.32,1014.32 UC.34@292.62,1014.32 ; UC.52@292.62,1296.92 378.08,1296.92 519.08,1155.92 534.2,1155.92 563.11,1127 v3(580,1127) 692.25,1127 759.25,1060 816.11,1060 847,1090.89 847,1118 852.92,1123.92 853,1123.92 ; UC.60@292.62,1422.52 226.52,1422.52 209,1405 134.89,1405 117,1422.89 117,1425 57,1485 60.5,1488.5 60.5,1521.11 61,1521.61 61,1648 80,1667 210,1667 226.67,1650.33 C4C.2@226.67,1622 254.67,1594 281,1594 v1(315,1560) ; UC.67@383.17,1544.47 383.17,1598.17 ; 383.47,1598.17 383.47,1722.47 399,1738 C6C.2@399,1753.33 ; v3(479,2925) 590.57,3036.57 J2.15@590.57,3186 J2.15@595,3181.57 ; UC.77@540.17,1544.47 540.17,1508.17 516,1484 516,1458 530,1444 566,1444 v1(603,1481) 618.67,1496.67 UC.82@618.67,1544.47 ; v3(761,1175) 817,1175 844.42,1202.42 ; 844.72,1202.72 UC.115@897.62,1202.72 ; 853,1124 853.22,1124.22 UC.120@897.62,1124.22 ; UC.128@897.62,998.62 952.38,998.62 v14(967,984) ; UC.102@897.62,1406.82 936.18,1406.82 949,1394 1006.5,1394 R2_C.1@1037.5,1425 ; UC.97@897.62,1486.62 924.62,1486.62 C1D.2@952,1514 ; J2.35@905.54,3186 905.54,3082.46 v14(938,3050) 968.53,3080.53 J2.39@968.53,3186 ; UD.52@1237.93,1296.92 1158.92,1296.92 1137,1275 1137,1217 1084,1164 1084,1133.89 1123.89,1094 1180,1094 1194.22,1108.22 1200.78,1108.22 1201.08,1108.52 UD.40@1237.93,1108.52 1311.48,1108.52 v3(1331,1089) ; UD.60@1237.93,1422.52 1309.48,1422.52 v11(1320,1412) ; C14C.2@1269,1995 1269,1968 v18(1312,1925) 1324.44,1937.44 C13C.2@1324.44,1995 ; v14(1283,3042) 1314.98,3073.98 J2.53@1314.98,3186 ; UD.67@1328.48,1544.47 1328.48,1719.82 C2C.2@1328.66,1720 1328.66,1774.66 v3(1333,1779) ; R_Trig_D.2@1368,2204.26 v14(1461.74,2204.26) ; C12C.2@1379.89,1995 1379.89,1965.11 v18(1420,1925) 1435.33,1940.33 C11C.2@1435.33,1995 ; J2.61@1440.97,3186 1440.97,3072.03 v14(1473,3040) 1503.96,3070.96 J2.65@1503.96,3186 ; J2.71@1598.6,3186 1598.6,3055.4 1652,3002 v14(1715,3002) 1724.42,3011.42 J2.79@1724.42,3186 ; C9D.2@1772.21,2147.69 1892.31,2147.69 v3(1894,2146) ; C8D.2@1772.21,2200.53 1832.53,2200.53 v3(1835,2203) ; C2D.2@1772.67,2461 1892,2461 v3(1894,2459) ; C4D.2@1772.79,2406.16 1833.84,2406.16 v3(1835,2405) ; C7D.2@1774,2252.71 1891.62,2252.71 v3(1894,2250.33) ; C6D.2@1774,2304.18 1834.82,2304.18 v3(1835,2304) ; C5D.2@1774,2357 1891.67,2357 v3(1894,2354.67) ; UD.128@1842.93,998.62 1891.38,998.62 v1(1895,995) ; UD.115@1842.93,1202.72 1946.58,1202.42 1954,1195 v3(1961,1195) ; UD.107@1842.93,1328.32 1894.25,1327.89 1925.11,1327.89 1945,1308 v3(1945,1292) ; UD.102@1842.93,1406.82 1936.18,1406.82 v14(1964,1379) ; UD.97@1842.93,1485.32 1885.32,1485.32 1907,1507 1907,1577 v3(1908,1578) ; Bf_D.5@1858.22,811.11 1824.18,777.07 R_BF1_D.2@1824.18,748.1 1843.08,767 v1(1868,767) ; v3@1908.5,1578.5 R2_D.1@1947,1579
  other v11: 365,1203 1310,1328 1783,1423
  other v12: 166,708 967,984 1057,1363 1473,3040
CLR: J2.13 UA.95 UB.95 UC.95 UD.95 | length 3566.8
  Top Layer w6: 367.17,1596.83 339,1625 339,1698 358,1717 v6(384,1717) ; UA.95@367.47,1544.47 367.47,1596.53 ; v2(1301,1613) 1312.78,1601.22 UB.95@1312.78,1544.47
  AUX Route Vert w6: v6(384,1717) 377,1724 377,2774.12 447,2844.12 447,2861 v4(469,2883)
  AUX Routing (LVDS) w6: v6(384,1717) 477,1624 v3(944,1624)
  AUX Route Horz w6: v3(944,1624) 947,1621 955.89,1621 982.89,1648 1131.11,1648 1166.11,1613 v2(1301,1613) 1747.15,1613 1759.15,1601 v5(1781,1601)
  Bottom Layer w6: v4(469,2883) 469,2890.89 449,2910.89 449,2945.49 528.09,3024.58 528.09,3070.09 559.08,3101.08 J2.13@559.08,3186 ; UC.95@822.77,1544.47 822.77,1583.77 ; 823.07,1583.77 823.07,1584.07 863,1624 v3(944,1624) ; UD.95@1768.08,1544.47 1768.08,1598 ; 1768.38,1598.3 1771.08,1601 v5(1781,1601)
DO_1: J2.19 UA.91 UB.91 UC.91 UD.91 | length 5353.5
  Top Layer w6: 429.97,2040.6 429.97,2047.22 551.75,2169 v4(554,2169) ; UA.91@430.27,1544.47 430.27,2045.27 ; UB.91@1375.58,1544.47 1375.58,2120.58 1419,2164 v1(1639,2164)
  AUX Route Vert w6: v4(554,2169) 554,2920 v4(555,2921)
  AUX Route Horz w6: v4(554,2169) 1634,2169 v1(1639,2164)
  Bottom Layer w6: v4(554,2169) 664.25,2169 720.25,2113 777.51,2113 841,2049.51 841,1907 887.06,1860.94 887.06,1700.06 779,1592 769,1592 759.97,1582.97 UC.91@759.97,1544.47 ; v4(555,2921) 555,2944.37 638.07,3027.44 638.07,3114.07 653.57,3129.57 J2.19@653.57,3186 ; v1(1639,2164) 1645.63,2164 1743,2066.63 1743,1949.65 1819,1873.65 1819,1702.5 1720.5,1604 1712,1604 1705.58,1597.58 ; UD.91@1705.28,1544.47 1705.28,1597.28
  other v6: 554,2169
DO_2: J2.21 UA.90 UB.90 UC.90 UD.90 | length 5165.2
  Top Layer w6: 445.97,2040.6 UA.90@445.97,1544.47 UA.90@446.27,1544.77 ; 446.27,2040.9 545.37,2140 v6(609.5,2141.5) ; UB.90@1391.28,1544.47 1391.28,2094 1433.28,2136 v1(1592,2136)
  AUX Route Vert w6: v4(594,2884) 588,2878 588,2814.89 594,2808.89 594,2548.11 573,2527.11 573,2310.11 603.5,2279.61 603.5,2261.39 603.5,2147.49 v6(609.5,2141.5)
  AUX Route Horz w6: v6(609.5,2141.5) 614.99,2136 v1(1592,2136)
  Bottom Layer w6: v4(594,2884) 594,2960.75 654.07,3020.82 654.07,3091.07 685.06,3122.06 J2.21@685.06,3186 ; v6(609.5,2141.5) 670.63,2140 713.63,2097 770.88,2097 825,2042.88 825,1900.37 871.06,1854.32 871.06,1706.68 772.37,1608 761,1608 744.27,1591.27 UC.90@744.27,1544.47 ; v1(1592,2136) 1651,2136 1727,2060 1727,1943.02 1803,1867.02 1803,1709.12 1713.88,1620 1700,1620 1689.88,1609.88 1689.88,1609.58 ; UD.90@1689.58,1544.47 1689.58,1609.58
  other v4: 609.5,2141.5
DO_3: J2.23 UA.89 UB.89 UC.89 UD.89 | length 5035.6
  Top Layer w6: UA.89@461.67,1544.47 463,2019 463,2035 539,2111 v6(636,2111) ; UB.89@1406.98,1544.47 1406.98,2075.98 1433,2102 v1@1637,2102
  AUX Route Vert w6: v6(636,2111) v4(636,2918)
  AUX Route Horz w6: v6(636,2111) 1632,2111 v1(1639,2104)
  Bottom Layer w6: v6(636,2111) 677,2111 707,2081 764.25,2081 809,2036.25 809,1893.75 855.06,1847.69 855.06,1713.31 765.75,1624 754.37,1624 728.57,1598.2 UC.89@728.57,1544.47 ; v4(636,2918) 636,2980.12 670.07,3014.19 670.07,3058.07 716.56,3104.56 J2.23@716.56,3186 ; v1(1639,2104) 1639,2098.74 1711,2026.74 1711,1936.39 1787,1860.39 1787,1715.75 1707.25,1636 1686,1636 1673.88,1623.88 UD.89@1673.88,1544.47
  other v4: 636,2111
DO_4: J2.25 UA.88 UB.88 UC.88 UD.88 | length 4847.1
  Top Layer w6: UA.88@477.37,1544.47 476.03,2017 535,2075.97 670.97,2075.97 v6(686,2079) ; UB.88@1422.68,1544.47 1422.68,2043.68 ; 1422.98,2043.68 1422.98,2043.98 1451,2072 v1(1591,2072)
  AUX Route Vert w6: v6(686,2079) v4(686,2887)
  AUX Route Horz w6: v6(686,2079) 677,2072 v1(1591,2072)
  Bottom Layer w6: v6(686,2079) 684,2065 757.63,2065 793,2029.63 793,1887.12 839.06,1841.06 839.06,1719.94 760.12,1641 746.87,1641 712.87,1607 UC.88@712.87,1544.47 ; v4(686,2887) 686,2982 748.06,3044.06 J2.25@748.06,3186 ; v1(1591,2072) 1596,2067 1648.11,2067 1695,2020.11 1695,1929.76 1771,1853.76 1771,1722.38 1700.62,1652 1663,1652 1658.78,1647.78 ; UD.88@1658.18,1544.47 1658.18,1647.18
  other v4: 686,2079
  other v23: 1591,2072
DO_5: J2.27 UA.87 UB.87 UC.87 UD.87 | length 4740.8
  Top Layer w6: UA.87@493.07,1544.47 493.97,1545.37 493.97,2011.43 ; 493.97,2011.97 525,2043 v4(716,2044) ; UB.87@1438.38,1544.47 1438.38,2015.38 1468,2045 v1(1639,2045)
  AUX Route Vert w6: v4(716,2044) v4(716,2922)
  AUX Route Horz w6: v4(716,2044) 709,2045 v1(1639,2045)
  Bottom Layer w6: UC.87@697.17,1544.47 697.17,1615.17 739,1657 753.49,1657 823.06,1726.57 823.06,1834.43 777,1880.49 777,2023 757,2043 v4(716,2044) ; v4(716,2922) 779.55,2985.55 J2.27@779.55,3186 ; v1(1639,2045) 1679,2005 1679,1923.14 1755,1847.14 1755,1729.01 1693.99,1668 1648,1668 1642,1662 ; UD.87@1642.48,1544.47 1642.48,1661.52
  other v6: 716,2044
DO_6: J2.29 UA.86 UB.86 UC.86 UD.86 | length 4545
  Top Layer w6: UA.86@508.77,1544.47 508.77,1998 ; 509.97,1999.2 519.77,2009 v1(753,2009) ; UB.86@1454.08,1544.47 1454.08,1995.08 1476,2017 v1(1591,2017)
  AUX Route Vert w6: v4(746,2885) 750,2881 750,2841.26 768,2823.26 768,2024 v1(753,2009)
  AUX Route Horz w6: v1(753,2009) 1583,2009 v1(1591,2017)
  Bottom Layer w6: UC.86@681.47,1544.47 681.47,1622.47 732,1673 746.86,1673 807.06,1733.19 807.06,1827.81 761,1873.86 761,2001 v1(753,2009) ; v4(746,2885) 746,2926 811.05,2991.05 J2.29@811.05,3186 ; v1(1591,2017) 1640.11,2017 1663,1994.11 1663,1916.51 1739,1840.51 1739,1735.63 1687.37,1684 1635.25,1684 1627.08,1675.82 ; UD.86@1626.78,1544.47 1626.78,1675.82
DO_7: J2.31 UA.85 UB.85 UC.85 UD.85 | length 4552.2
  Top Layer w6: UA.85@524.47,1544.47 524.47,1974 ; 524.77,1974.3 533.47,1983 v1(710,1983) ; UB.85@1469.78,1544.47 1469.78,1973.78 1483,1987 v1(1639,1987)
  AUX Route Vert w6: v1(710,1983) 772,1983 784,1995 784,2829.89 766,2847.89 766,2866.11 787,2887.11 v4(787,2920)
  AUX Route Horz w6: v1(710,1983) 1635,1983 v1(1639,1987)
  Bottom Layer w6: UC.85@665.77,1544.47 665.77,1631.77 723,1689 740.24,1689 791.06,1739.82 791.06,1821.18 745,1867.24 745,1951 713,1983 v1(710,1983) ; v4(787,2920) 843,2976 843,3185.54 J2.31@842.54,3186 ; UD.85@1611.08,1544.47 1611.08,1682.45 ; 1611.38,1682.75 1628.63,1700 1680.74,1700 1723,1742.26 1723,1833.88 1639,1917.88 v1(1639,1987)
DO_8: J2.33 UA.84 UB.84 UC.84 UD.84 | length 4434.5
  Top Layer w6: UA.84@540.17,1544.47 540.17,1946 ; 540.47,1946 540.47,1946.3 555.17,1961 575.17,1941 v1(689,1941) ; UB.84@1485.48,1544.47 1485.48,1943 ; 1485.78,1943 1485.78,1943.3 1501.48,1959 v1(1591,1959)
  AUX Route Vert w6: v1(689,1941) 689,1955 695,1961 773.37,1961 831,2018.63 831,2876 v4(822,2885)
  AUX Route Horz w6: v1(689,1941) 707,1959 v1(1591,1959)
  Bottom Layer w6: UC.84@650.07,1544.47 650.07,1639.07 716,1705 733.61,1705 775.06,1746.45 775.06,1814.55 729,1860.61 729,1922 710,1941 v1(689,1941) ; v4(822,2885) 874.04,2937.04 J2.33@874.04,3186 ; v1(1591,1959) 1591,1894 1622,1863 1671.25,1863 1707,1827.25 1707,1748.89 1674.11,1716 1622,1716 1595.38,1689.38 UD.84@1595.38,1544.47
DO_9: J2.58 UA.76 UB.76 UC.76 UD.76 | length 4083.1
  Top Layer w6: UA.76@665.77,1544.47 665.77,1778.77 673,1786 v1(673,1817) ; v10(1375,2998) 1375,3178.98 1380,3183.98 J2.58@1377.98,3186 ; 1610.78,1606.92 1610.78,1607.22 ; UB.76@1611.08,1544.47 1611.08,1606.92 1610.78,1607.22 ; v1(1629,1803) 1629,1772.63 1611.73,1755.36 1611.73,1651.36 1607,1646.63 1607,1611 1610.78,1607.22
  AUX Routing (LVDS) w6: v10(1375,2998) 1375,2944.05 1617,2702.05 1617,1977.89 1629,1965.89 v1(1629,1803)
  AUX Route Horz w6: v1(673,1817) 681,1825 1607,1825 v1(1629,1803)
  Bottom Layer w6: UC.76@524.47,1544.47 524.47,1942 ; 524.77,1942 524.77,1947.21 541.47,1963.91 564.83,1963.91 615.75,1913 633,1913 680,1866 680,1824 v1(673,1817) ; UD.76@1469.78,1544.47 1470.08,1544.77 1470.08,1789.08 1488.5,1807.5 1534.13,1807.5 1543.63,1798 1588.37,1798 1597.87,1807.5 1608.39,1807.5 1612.89,1803 v1(1629,1803)
DO_10: J2.52 UA.75 UB.75 UC.75 UD.75 | length 4396.1
  Top Layer w6: UA.75@681.47,1544.47 681.47,1757.47 ; 681.77,1757.77 v1(705,1781) ; v10(1283,3101) 1283,3185.51 J2.52@1283.49,3186 ; 1626.48,1618.22 1626.48,1618.52 1623,1622 1623,1640 1627.73,1644.73 1627.73,1748.73 v1(1669,1790) ; UB.75@1626.78,1544.47 1626.78,1618.22
  AUX Routing (LVDS) w6: v10(1283,3101) 1346,3101 1388,3059 1388,3030.89 1402,3016.89 1402,2984.26 1669,2717.26 v1(1669,1790)
  AUX Route Horz w6: v1(705,1781) 733,1809 1591.89,1809 1619.89,1781 1638.11,1781 1654.11,1797 1662,1797 v1(1669,1790)
  Bottom Layer w6: UC.75@508.77,1544.47 508.77,1954.14 ; 509.07,1954.14 509.07,1968.07 531,1990 561.37,1990 622.37,1929 639.63,1929 696,1872.63 696,1848.35 705,1839.35 v1(705,1781) ; UD.75@1454.08,1544.47 1453,1545.55 1453,1797 1486,1830 1534.26,1830 1550.26,1814 1581.74,1814 1597.74,1830 1616.38,1830 1617.38,1831 1658,1831 1669,1820 v1(1669,1790)
DO_11: J2.60 UA.74 UB.74 UC.74 UD.74 | length 4476.1
  Top Layer w6: UA.74@697.17,1544.47 697.17,1635.17 ; 697.47,1635.17 697.47,1671.54 ; 697.77,1671.84 697.47,1671.54 ; v1(726,1738) 726,1732 697.47,1703.47 697.47,1671.54 ; J2.60@1409.47,3186 1410,3185.47 v10(1410,3040) ; UB.74@1642.48,1544.47 1642.48,1630.52 1643.73,1631.78 1643.73,1729.73 1652,1738 v1(1665,1738)
  AUX Routing (LVDS) w6: v10(1410,3040) 1418,3032 1418,2990.89 1691,2717.89 1691,1780.89 1665,1754.89 v1(1665,1738)
  AUX Route Horz w6: v1(726,1738) 734,1746 1657,1746 v1@1661,1742
  Bottom Layer w6: UC.74@493.07,1544.47 493.07,1976.07 523,2006 568,2006 629,1945 646.25,1945 712,1879.25 712,1862 713,1861 713,1853.98 758,1808.98 758,1762 734,1738 v1(726,1738) ; 1437,1585 1437,1803.63 1479.37,1846 1540.89,1846 1556.89,1830 1575.11,1830 1592.11,1847 1664.63,1847 1685,1826.63 1685,1805.11 1691,1799.11 1691,1758 1671,1738 v1(1665,1738) ; UD.74@1438.38,1544.47 1438.38,1583.62
DO_12: J2.62 UA.73 UB.73 UC.73 UD.73 | length 3760.6
  Top Layer w6: v1(627,1350) 625,1352 625,1417 712.87,1504.87 UA.73@712.87,1544.47 ; v6(1440,3000) 1440.97,3000.97 J2.62@1440.97,3186 ; v2(1571,1350) 1571,1416 1658.18,1503.18 UB.73@1658.18,1544.47
  AUX Route Vert w6: v6(1440,3000) 1440,2998 1477,2961 1522,2961 1583,2900 1583,2158 1582.89,2158 1559,2134.11 1559,1951.01 1582.03,1927.98 1583,1866.11 1588,1861.11 1588,1715.89 1571,1698.89 v2(1571,1350)
  AUX Route Horz w6: v1(627,1350) 646.11,1350 695,1398.89 695,1401.11 707.89,1414 783.38,1414 800.38,1431 871.62,1431 888.62,1414 905.12,1414 920.84,1429.72 995.65,1429.72 1056.37,1369 1267.38,1369 1274.38,1376 1545,1376 v2(1571,1350)
  Bottom Layer w6: UC.73@477.37,1544.47 477.37,1398.63 527,1349 626,1349 v1(627,1350)
  other v17: 1571,1350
